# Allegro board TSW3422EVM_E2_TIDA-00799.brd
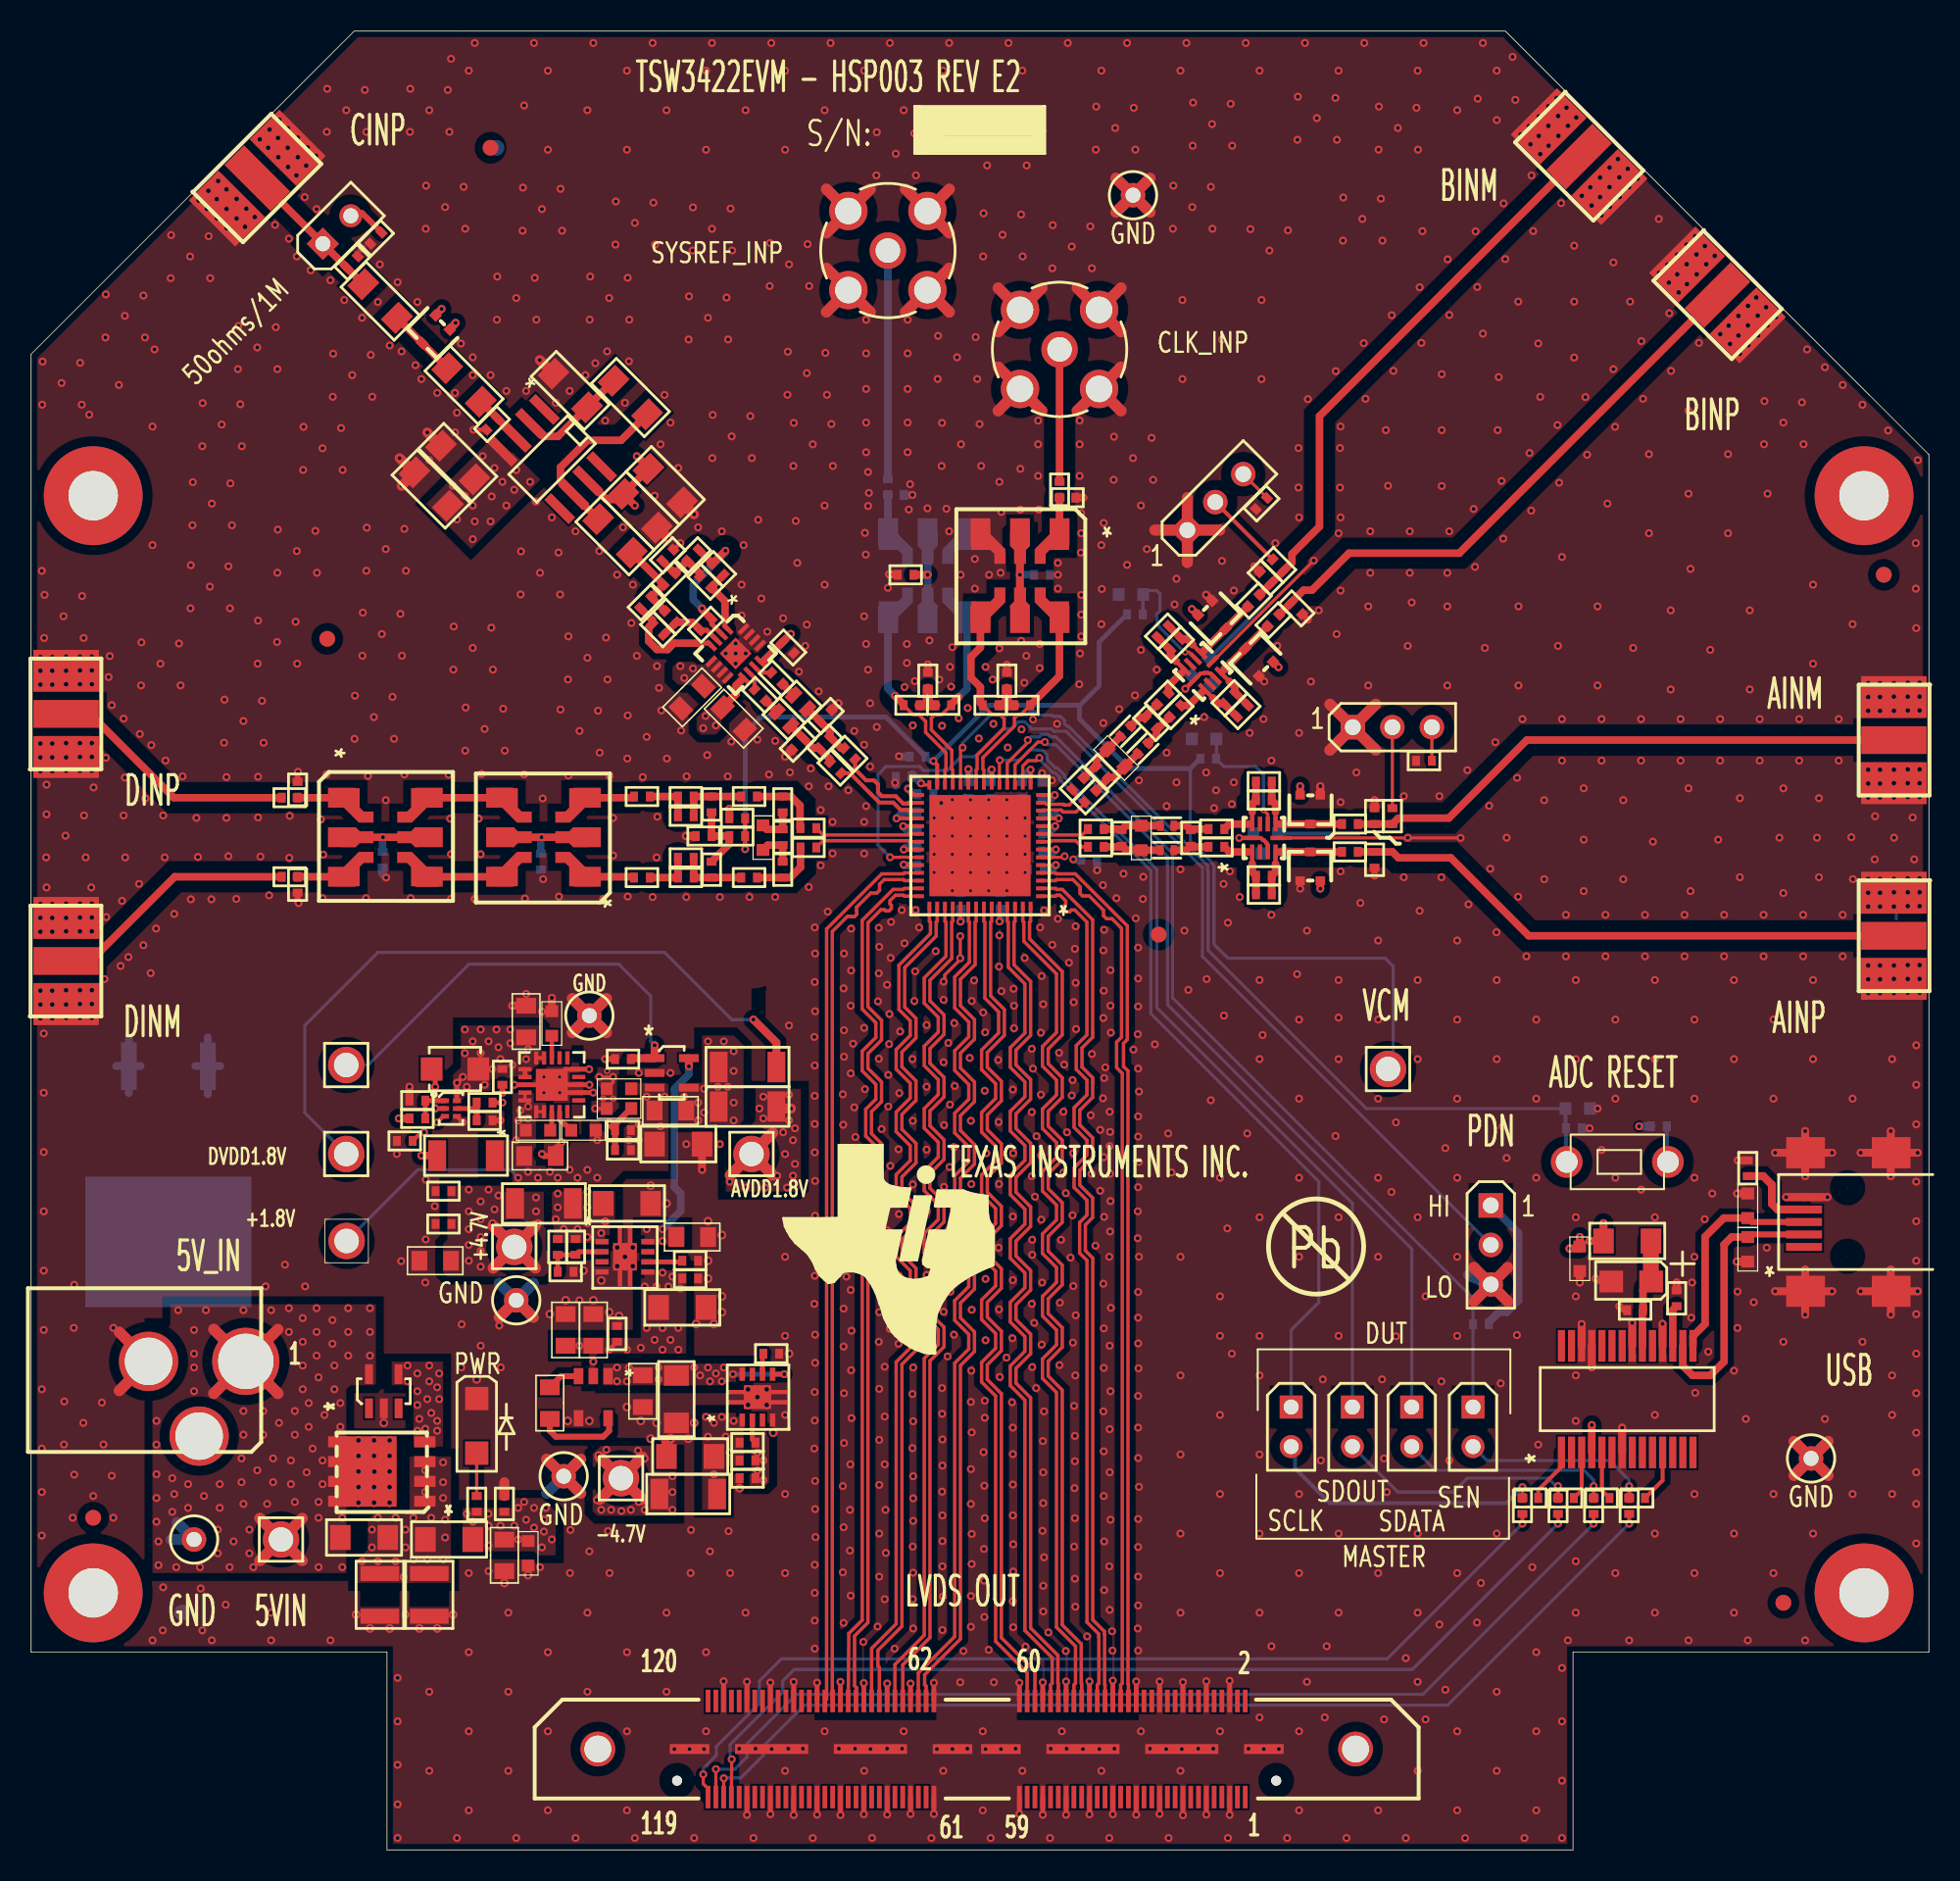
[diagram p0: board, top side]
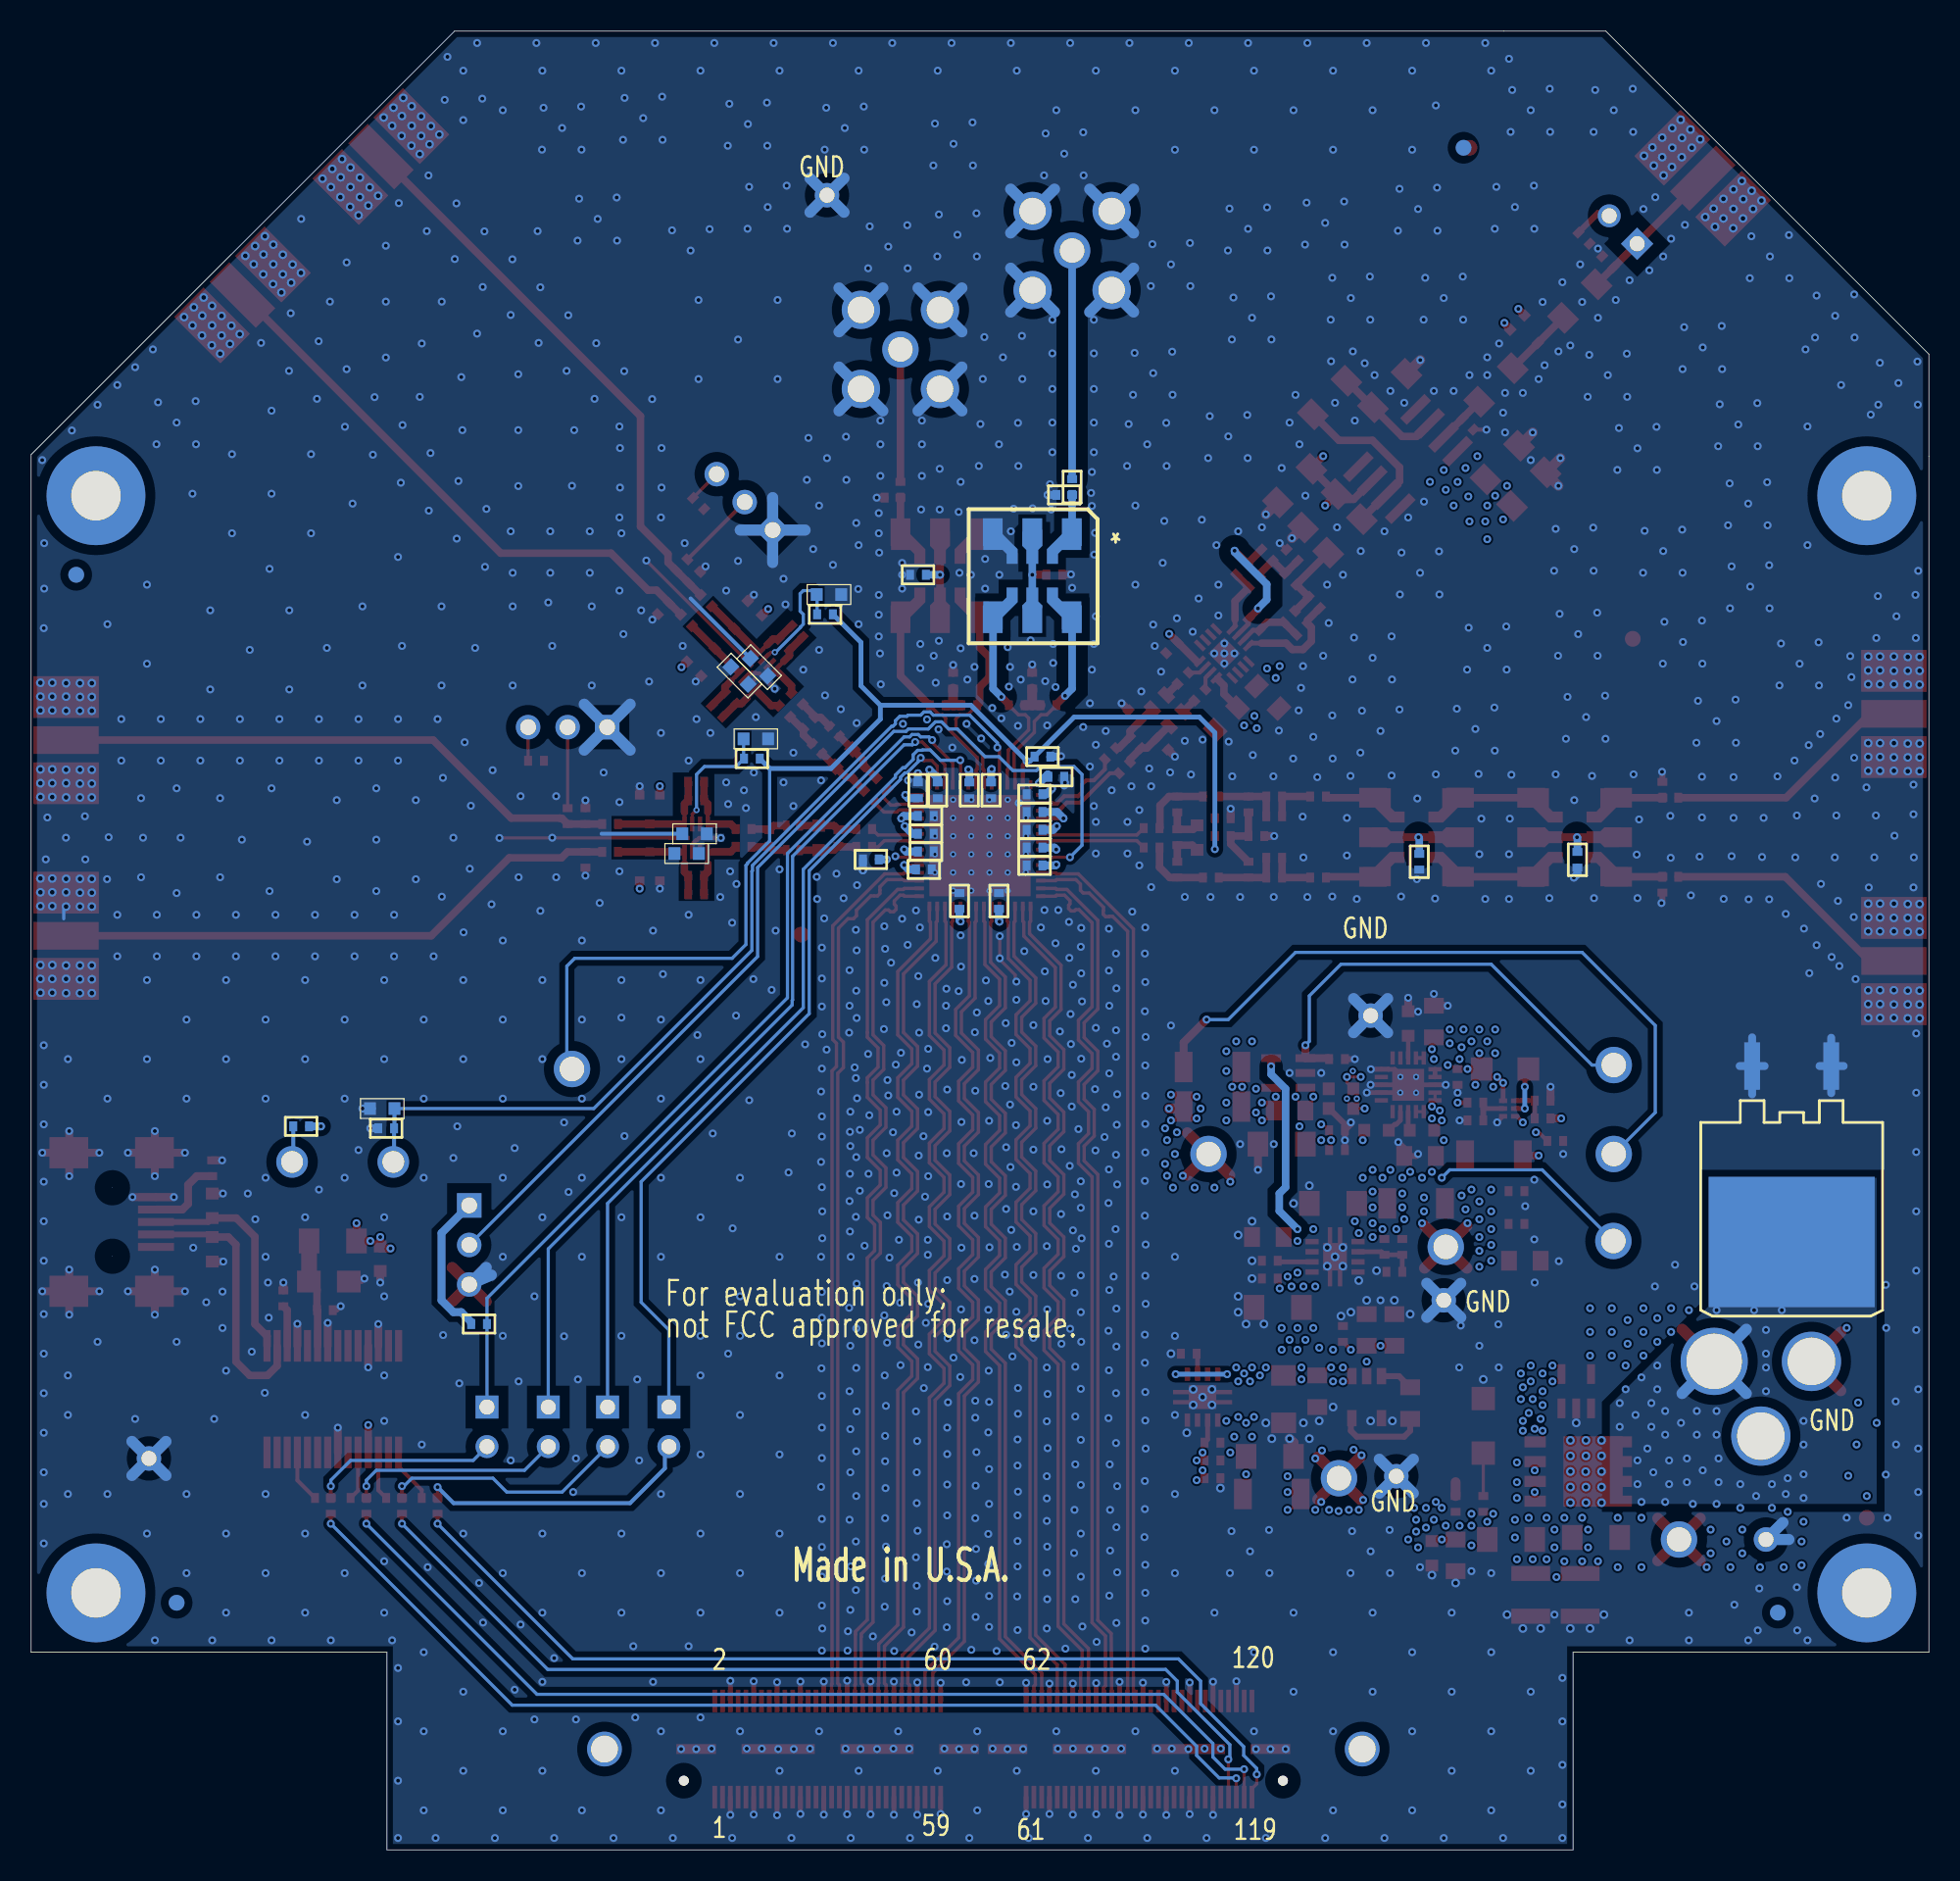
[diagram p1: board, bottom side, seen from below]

Outline 121.92 x 116.84 mm; copper layers: TOP, LYR2_GND, LYR3_PWR, LYR4_PWR, LYR5_GND, BOTTOM. Coordinates in mm from the lower left corner of the outline.
Outline path: 0,96.09 0,12.7 22.86,12.7 22.86,0 99.06,0 99.06,12.7 121.92,12.7 121.92,89.64 94.72,116.84 20.75,116.84 0,96.09

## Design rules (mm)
net group AIN: nets AINM AINP
net group BIN: nets BINM BINP
net group CIN: nets CINM CINP
net group CLKIN: nets CLKINM CLKINP
net group DA0: nets DA0M DA0P
net group DA1: nets DA1M DA1P
net group DB0: nets DB0M DB0P
net group DB1: nets DB1M DB1P
net group DC0: nets DC0M DC0P
net group DC1: nets DC1M DC1P
net group DCLK: nets DCLKM DCLKP
net group DD0: nets DD0M DD0P
net group DD1: nets DD1M DD1P
net group DIN: nets DINM DINP
net group FCLK: nets FCLKM FCLKP
net group SYSREF: nets SYSREFM SYSREFP

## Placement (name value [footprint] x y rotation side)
C1  .1uF  [0402]  39.24 62.46 0 top
C2  11pF  [0402]  48.28 65.05 90 top
C3  .1uF  [0402]  43.2 65.13 0 top
C4  .1uF  [0402]  45.36 66.27 0 top
C5  .1uF  [0402]  22.58 63.61 90 bottom
C6  .1uF  [0402]  32.74 63.48 90 bottom
C7  .1uF  [0402]  39.24 67.67 0 top
C8  5.6pF  [0402]  40.28 78.41 135 top
C9  16pF  [0402]  40.99 81.65 45 top
C10  5.6pF  [0402]  44.14 82.28 315 top
C11  5pF  [0402]  29.61 91.6 225 top
C12  82pF  [0402]  50.96 71.14 45 top
C13  5.6pF  [0402]  43.36 78.71 45 top
C14  .1uF  [1206]  27.41 89.13 135 top
C15  6.8uF  [1206]  25.7 87.42 135 top
C16  .1uF  [1206]  39.13 86.03 315 top
C17  6.8uF  [1206]  40.74 87.65 315 top
C18  .1uF  [0402]  48.64 77.24 315 top
C19  10uF  [0805]  42.47 74.04 225 top
C20  56pF  [0402]  71.95 72.39 315 top
C21  180pF  [0603]  69.7 70.15 315 top
C22  .01uF  [0603]  70.66 80.65 180 bottom
C23  10uF  [0805]  31.8 53.21 90 top
C24  0.01uF  [0603]  32.56 46.23 0 top
C25  56pF  [0402]  74.5 65.01 270 top
C26  180pF  [0603]  71.32 65.01 270 top
C27  .01uF  [0603]  75.36 71.37 180 bottom
C28  22uF  [0805]  32.69 44.58 0 top
C29  0.01uF  [0603]  33.45 53.09 90 top
C30  .1uF  [0402]  57.45 65.53 0 bottom
C31  .1uF  [0402]  57.45 66.67 0 bottom
C32  .1uF  [0402]  57.45 67.82 0 bottom
C33  .1uF  [0402]  56.06 68.94 180 bottom
C34  .1uF  [0402]  60.25 68.07 270 bottom
C35  .1uF  [0402]  61.65 68.07 270 bottom
C36  .1uF  [0402]  63.68 68.07 270 bottom
C37  .1uF  [0402]  67.97 63.63 0 bottom
C38  .1uF  [0402]  64.44 64.14 180 bottom
C39  .1uF  [0402]  57.45 64.39 0 bottom
C40  .1uF  [0402]  64.44 66.42 180 bottom
C41  .1uF  [0402]  64.44 65.28 180 bottom
C42  .1uF  [0402]  64.95 68.07 90 bottom
C43  .22uF  [0402]  64.57 62.99 180 bottom
C44  .22uF  [0402]  62.28 60.96 90 bottom
C45  .22uF  [0402]  59.74 60.96 90 bottom
C46  .22uF  [0402]  57.45 63.25 0 bottom
C47  .01uF  [0603]  99.36 47.62 0 bottom
C48  .1uF  [0402]  56.95 70.23 180 bottom
C49  .1uF  [0402]  66.07 87.38 90 top
C50  .1uF  [0402]  62.69 75.11 90 top
C51  .1uF  [0805]  25.96 37.85 180 top
C52  .1uF  [0402]  64.94 81.92 0 bottom
C53  .1uF  [0402]  55.04 87.55 90 bottom
C54  .1uF  [0402]  57.61 75.11 90 top
C55  .1uF  [0402]  26.49 42.32 180 top
C56  0  [0402]  56.18 81.92 180 top
C57  .01uF  [0603]  99.49 37.97 270 top
C58  .1uF  [0402]  103.05 34.67 180 top
C59  4.7uF  [TANT_A]  102.79 36.51 180 top
C60  47pF  [0603]  110.29 41.38 90 top
C61  47pF  [0603]  110.29 38.58 270 top
C62  .1uF  [0402]  105.71 35.43 90 top
C63  47uF  [1210]  25.58 16.38 270 top
C64  22uF  [1210]  22.4 16.38 90 top
C65  10uF  [0805]  30.4 18.92 270 top
C66  1.0uF  [0603]  31.93 19.05 270 top
C67  .1uF  [0402]  30.4 22.23 270 top
C68  2.2uF  [0402]  24 45.54 180 top
C69  .1uF  [0402]  38.02 46.23 0 top
C70  4.7uF  [0402]  30.28 49.66 270 top
C71  .1uF  [0402]  26.49 40.21 180 top
C72  10uF  [1206]  41.58 45.34 0 top
C75  10uF  [0805]  42.47 39.37 0 top
C76  .1uF  [0402]  42.34 36.7 180 top
C77  10uF  [1206]  41.83 34.85 0 top
C78  10uF  [1206]  38.28 41.53 0 top
C79  .01uF  [0402]  34.98 38.73 270 top
C80  .01uF  [0402]  42.34 37.85 0 top
C81  .01uF  [0402]  38.02 44.96 180 top
C82  10uF  [0805]  36.12 33.4 90 top
C83  .1uF  [0402]  37.64 33.15 270 top
C84  1uF  [0805]  34.34 33.4 90 top
C86  10uF  [1206]  41.45 28.96 270 top
C87  10uF  [1206]  42.34 25.27 180 top
C88  .01uF  [0402]  46.02 26.16 0 top
C89  1uF  [0402]  47.55 31.88 0 top
C90  1uF  [0805]  39.29 29.46 270 top
C91  1uF  [0805]  33.32 28.7 90 top
C94  .1uF  [0603]  75.15 75.98 45 bottom
C95  .1uF  [0603]  76.41 75.44 45 bottom
C96  .1uF  [0603]  79.81 64.01 0 bottom
C97  .1uF  [0603]  79.3 65.28 0 bottom
C98  .1uF  [0805]  45.14 72.67 315 top
C99  .1uF  [0402]  79.2 68.63 0 top
C100  .1uF  [0402]  72.71 78.27 45 top
C101  .1uF  [0402]  77.83 73.15 45 top
C102  .1uF  [0402]  79.2 61.39 0 top
C103  1uF  [0402]  79.04 86.49 225 top
C104  1uF  [0402]  89.48 69.97 180 top
D1  BAV99W  [SOT_323]  25.78 97.46 135 top
D2  BAV99W  [SOT_323]  78.67 76.53 45 top
D3  BAV99W  [SOT_323]  82.18 63.19 0 top
D4  LED GREEN  [LED_1206]  28.63 27.24 90 top
D5  MBRB2515L  [DIODE_MBRB2515L]  8.81 44.7 90 bottom
D6  BAV99W  [SOT_323]  76.09 79.11 225 top
D7  BAV99W  [SOT_323]  82.18 66.83 180 top
F1  FUSE 2.0A 63V FAST  [1206]  21.39 20.07 0 top
FB1  60 OHM @ 100MHz  [1206]  102.54 39.12 180 top
FB2  60 OHM @ 100MHz  [1206]  26.85 19.94 180 top
FB3  1K @ 100MHz  [1806]  46.02 50.29 180 top
FB4  1K @ 100MHz  [1806]  32.94 41.53 0 top
FB5  1K @ 100MHz  [1806]  42.21 22.86 0 top
FB6  1K @ 100MHz  [1806]  27.94 44.6 0 top
FB7  1K @ 100MHz  [1806]  46.02 47.75 180 top
J1  SMA_END_RND  [SMA_RECP_250X250]  2.25 57.1 0 top
J2  SMA_END_RND  [SMA_RECP_250X250]  2.25 72.98 0 top
J3  SMA_END_RND  [SMA_RECP_250X250]  14.53 107.39 315 top
J4  SMA_END_RND  [SMA_RECP_250X250]  108.34 99.89 225 top
J5  SMA_END_RND  [SMA_RECP_250X250]  99.45 108.78 225 top
J6  SMA_END_RND  [SMA_RECP_250X250]  119.67 58.72 180 top
J7  SMA_END_RND  [SMA_RECP_250X250]  119.67 71.29 180 top
J8  SMB_THVT_REC  [SMA_THVT_312X312]  66.07 96.39 270 top
J10  SMB_THVT_REC  [SMA_THVT_312X312]  55.04 102.74 0 top
J12  QTH-060-01-F-D-A-RT1  [CON_SMVT_120POS_QTH_SAMTEC_RT1]  79.96 4.45 180 top
J13  CONN, USB MINI AB, SMT  [CON_SMRT_USBMNE20_F]  117.35 40.34 180 top
J14  CONN JACK PWR  [CON_RAPC722_JACK_THVT_3]  10.67 31.38 270 top
JP1  HEADER, 2POS, .100  [HDR_THVT_1X2_100_M]  18.74 103.18 135 top
JP2  HEADER, 3POS, .100  [HDR_THVT_1X3_100_M]  93.78 41.4 0 top
JP3  HEADER, 2POS, .100  [HDR_THVT_1X2_100_M]  80.95 28.45 0 top
JP4  HEADER, 2POS, .100  [HDR_THVT_1X2_100_M]  88.7 28.45 0 top
JP5  HEADER, 2POS, .100  [HDR_THVT_1X2_100_M]  92.63 28.45 0 top
JP6  HEADER, 2POS, .100  [HDR_THVT_1X2_100_M]  84.89 28.45 0 top
JP7  HEADER, 3POS, .100  [HDR_THVT_1X3_100_M]  74.28 84.79 135 top
JP8  HEADER, 3POS, .100  [HDR_THVT_1X3_100_M]  84.91 72.13 90 top
L1  39nH  [0402]  42.06 63.73 180 top
L2  11pF  [0603]  47.01 65.03 270 top
L3  39nH  [0402]  42.06 66.4 180 top
L4  240nH  [IND_0603]  48.36 72.67 315 top
L5  240nH  [IND_0603]  49.44 73.74 315 top
L6  390nH  [IND_0402]  70.32 71.87 225 top
L7  390nH  [IND_0402]  71.43 70.76 225 top
L8  390nH  [IND_0402]  72.97 65.8 180 top
L9  390nH  [IND_0402]  72.97 64.22 180 top
L10  2.2uH  [1008]  27.23 50.17 180 top
NOREF  -  [unnamed]  19.02 77.8 0 top
NOREF#2  -  [#2]  80.52 37.49 0 top
NOREF#3  -  [#2]  0 12.7 0 top
NOREF#4  -  [unnamed#3]  3.99 87 0 top
NOREF#5  -  [unnamed]  119.02 81.92 0 top
NOREF#6  -  [unnamed]  29.51 109.35 0 top
NOREF#7  -  [#2]  -294.27 -158.75 0 top
NOREF#8  -  [unnamed]  3.99 21.34 0 top
NOREF#9  -  [unnamed#3]  117.75 87 0 top
NOREF#10  -  [#2]  3.99 16.51 90 top
NOREF#11  -  [#2]  22.86 0 0 top
NOREF#12  -  [#2]  -286.46 355.6 0 top
NOREF#13  -  [#2]  3.99 16.51 0 top
NOREF#14  -  [#2]  18.17 -22.55 0 top
NOREF#15  -  [#2]  -14.76 124.49 0 top
NOREF#16  -  [unnamed#3]  117.75 16.51 0 top
NOREF#17  -  [#2]  49.7 109.54 0 top
NOREF#18  -  [#2]  -276.43 355.97 0 top
NOREF#19  -  [#2]  0 12.7 0 top
NOREF#20  -  [#2]  22.86 0 90 top
NOREF#21  -  [#2]  0 12.7 0 top
NOREF#22  -  [#2]  20.75 116.84 0 top
NOREF#23  -  [#2]  141.38 123.77 0 top
NOREF#24  -  [#2]  141.38 -14.66 0 top
NOREF#25  -  [#2]  -294.13 -159.02 0 top
NOREF#26  -  [#2]  0 12.7 90 top
NOREF#27  -  [unnamed]  112.57 15.88 0 top
NOREF#28  -  [unnamed]  72.44 58.8 0 top
NOREF#29  -  [unnamed#3]  3.99 16.51 0 top
NOREF#30  -  [#2]  3.99 16.51 90 top
NOREF#31  -  [#2]  562.28 -119.51 0 top
NOREF#32  -  [#2]  94.72 116.84 0 top
NOREF#33  -  [#2]  3.99 87 0 top
NOREF#34  -  [#2]  134.64 34.35 0 top
NOREF#35  -  [#2]  99.06 0 90 top
NOREF#36  -  [#2]  81.31 35.03 180 bottom
NOREF#37  -  [unnamed]  9.7 15.24 180 bottom
NOREF#38  -  [unnamed]  29.9 109.35 180 bottom
NOREF#39  -  [unnamed]  112.57 15.88 180 bottom
NOREF#40  -  [unnamed]  119.02 81.92 180 bottom
NOREF#41  -  [#2]  111.61 14.66 180 bottom
Q1  CSD18532Q5  [SON_Q5B_8]  22.53 24.31 180 top
R1  49.9  [0402]  42.06 62.46 0 top
R2  0  [0402]  46.13 62.46 0 top
R3  0  [0402]  49.94 64.39 0 top
R4  0  [0402]  16.61 62.51 0 top
R5  49.9  [0402]  48.28 62.97 90 top
R6  24.9  [0402]  43.71 62.97 90 top
R7  0  [0402]  17.12 62.01 270 top
R8  0  [0402]  45.36 65.13 0 top
R9  0  [0402]  16.61 67.59 0 top
R10  24.9  [0402]  43.71 67.16 90 top
R11  49.9  [0402]  48.28 67.16 90 top
R12  0  [0402]  17.12 68.1 90 top
R13  49.9  [0402]  42.06 67.67 0 top
R14  0  [0402]  46.13 67.67 0 top
R15  0  [0402]  49.94 65.64 0 top
R16  200  [1206]  38.5 93.3 315 top
R17  249  [0402]  39.49 80.14 225 top
R18  442  [1206]  37.51 84.41 315 top
R19  542  [0402]  41.08 79.22 315 top
R20  80.6  [0402]  46.83 74.19 315 top
R21  5.1  [0402]  51.68 69.52 315 top
R22  150  [1206]  22.42 99.5 315 top
R23  5.1  [0402]  67.24 68.49 225 top
R24  422  [0402]  68.81 69.25 135 top
R25  316  [0402]  49.26 71.05 45 top
R26  5.1  [0402]  68.04 67.68 225 top
R27  542  [0402]  42.52 83.17 45 top
R28  200  [1206]  34.64 93.75 135 top
R29  249  [0402]  43.33 81.47 315 top
R30  442  [0402]  40.9 83.17 225 top
R31  49.9  [0402]  22.15 103.54 225 top
R32  1M  [0402]  20.63 102.01 225 top
R33  80.6  [0402]  47.91 75.27 315 top
R34  5.1  [0402]  52.58 70.42 315 top
R35  316  [0402]  51.05 72.85 225 top
R36  402  [0402]  76.99 74 225 top
R37  402  [0402]  73.55 77.43 225 top
R38  61.9  [0402]  81.29 79.75 315 top
R39  34.8  [0402]  72.71 73.96 225 top
R40  162  [0402]  79.81 78.99 225 top
R41  49.9  [0402]  80.12 82.54 135 top
R42  162  [0402]  78.55 80.25 225 top
R43  34.8  [0402]  73.52 73.15 225 top
R44  61.9  [0402]  79.31 81.73 135 top
R45  100  [0402]  70.92 79.38 0 bottom
R46  402  [0402]  79.2 62.58 180 top
R47  402  [0402]  79.2 67.44 180 top
R48  61.9  [0402]  86.31 63.61 270 top
R49  34.8  [0402]  76.15 65.58 180 top
R50  5.1  [0402]  68.4 65.58 180 top
R51  162  [0402]  84.72 64.11 180 top
R52  162  [0402]  84.72 65.9 180 top
R53  34.8  [0402]  76.15 64.44 180 top
R54  61.9  [0402]  86.31 66.41 90 top
R55  100  [0402]  75.62 70.1 0 bottom
R56  1k  [0402]  93.14 33.78 180 bottom
R57  1k  [0402]  104.57 46.48 0 bottom
R58  10k  [0402]  99.11 46.36 0 bottom
R59  49.9  [0402]  66.58 86.87 0 top
R60  100  [0402]  63.68 73.53 0 top
R61  100  [0402]  61.65 73.53 0 top
R62  422  [0402]  70.05 65.01 90 top
R63  49.9  [0402]  55.55 87.05 0 bottom
R64  100  [0402]  58.6 73.53 0 top
R65  100  [0402]  56.57 73.53 0 top
R67  0  [0402]  95.81 22.1 90 top
R68  0  [0402]  100.38 22.1 90 top
R69  0  [0402]  98.09 22.1 90 top
R70  0  [0402]  102.67 22.1 90 top
R71  22  [0402]  96.32 22.61 0 top
R72  22  [0402]  100.89 22.61 0 top
R73  22  [0402]  98.6 22.61 0 top
R74  0  [0402]  110.29 43.79 90 top
R75  22  [0402]  103.17 22.61 0 top
R76  1k  [0402]  28.63 22.23 90 top
R77  0  [0402]  29.13 48.01 180 top
R78  0  [0402]  24.82 46.99 0 top
R79  0  [0402]  29.13 46.86 0 top
R80  0  [0402]  24.82 48.13 180 top
R81  10k  [0603]  35.48 46.23 180 top
R82  25.5K  [0402]  38.02 50.8 180 top
R83  34.8k  [0402]  33.83 38.73 270 top
R84  12k  [0402]  34.34 37.13 0 top
R85  649k  [0402]  46.02 25.02 0 top
R86  215k  [0402]  46.02 23.88 180 top
R87  5.1k  [0603]  37.77 48.89 0 top
R88  0.2  [0805]  41.07 47.5 180 top
R89  49.9  [1206]  27.81 94.11 315 top
R90  10k  [0603]  37.77 47.62 0 top
R91  5.1  [0402]  68.4 64.44 180 top
R92  49.9  [0402]  87.45 66.41 90 top
SW1  SW, PUSHBUTTON  [SW_RESET_PTS635]  101.9 44.2 0 top
T1  ADT1-1WT+  [TFMR_6_RF_DUAL_FOOTPRINT]  22.76 65.05 270 top
T2  ADT1-1WT+  [TFMR_6_RF_DUAL_FOOTPRINT]  32.92 65.05 90 top
T3  ADT4-6WT+  [TFMR_6_RF_DUAL_FOOTPRINT]  63.53 81.86 180 top
T4  ADT4-6WT+  [TFMR_6_RF_DUAL_FOOTPRINT]  57.6 81.86 0 bottom
TP1  RED  [TESTPOINT_62DRILL_THM]  87.17 50.17 0 top
TP2  RED  [TESTPOINT_62DRILL_THM]  16.05 19.94 0 top
TP3  BLK  [TP_THVT_060_RND_GND]  10.46 19.94 0 top
TP4  RED  [TESTPOINT_62DRILL_THM]  20.24 50.42 0 top
TP5  RED  [TESTPOINT_62DRILL_THM]  31.04 38.73 0 top
TP6  BLK  [TP_THVT_060_RND_GND]  35.86 53.59 0 top
TP7  RED  [TESTPOINT_62DRILL_THM]  37.9 23.88 0 top
TP8  BLK  [TP_THVT_060_RND_GND]  31.17 35.31 0 top
TP9  BLK  [TP_THVT_060_RND_GND]  34.21 24 0 top
TP10  BLK  [TP_THVT_060_RND_GND]  70.79 106.3 0 top
TP11  RED  [TESTPOINT_62DRILL_THM]  46.28 44.7 0 top
TP12  RED  [TESTPOINT_62DRILL_THM]  20.24 44.7 0 top
TP13  RED  [TESTPOINT_62DRILL_THM]  20.27 39.12 0 top
TP14  BLK  [TP_THVT_060_RND_GND]  114.35 25.15 0 top
U1  OPA656UB  [SO_8_197X157_50]  33.47 89.35 315 top
U2  THS4541  [VQFN_16_124X124_PWRPAD]  45.26 76.86 315 top
U3  THS4541  [QFN_10_83X83_RUN]  75.27 75.71 135 top
U4  THS4541  [QFN_10_83X83_RUN]  79.2 65.01 90 top
U5  ADC3422  [QFN_56_319X319_0P5MM]  60.96 64.52 180 top
U6  FT245RL  [SSOP_28_413X221_26]  102.54 28.96 90 top
U7  TPS2400  [DBV5]  22.66 29.46 90 top
U8  TPS6223X  [SON_6_DRY_1P5MMX1P0MM]  26.97 47.62 0 top
U9  TPS7A8300  [VQFN_20_138X138_0P50_RGR]  33.45 49.15 90 top
U10  TPS7A4901  [SON_8_3MMX3MM_0P65MM]  38.15 38.1 0 top
U11  TPS60403  [SOT-23_5_63X114_DBV]  36.12 29.08 270 top
U12  TPS7A3001  [SON_8_3MMX3MM_0P65MM]  46.66 29.08 90 top
U13  INA138  [DBV5]  41.16 49.91 0 top

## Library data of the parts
C1 C7 = CAP_0402_0.1uF: tolerance: 10%
C2 = CAP0603: tolerance: 1%
C3 C4 = CAP_0402_0.1uF_H: tolerance: 10%
C5 C6 C50 C52 C54 C99-C102 = CAP0603: tolerance: 10%
C8 C10 C13 = CAP_0402_5.6pF
C9 = CAP_0402_16pF
C11 = CAP_0402_5pF
C12 = CAP_0402_82pF
C14 C16 = CAP_1206_.1uF
C15 C17 = CAP_1206_6.8uF
C18 C55 C71 = CAP_0402_0.1uF
C19 = CAP_0805_10uF_16V: tolerance: 10%, 10V, X7R
C20 C25 = CAP_0402_56pF
C21 C26 = CAP_0603_180pF_.1%
C22 C24 C27 C29 = CAP_0603_0.01uF
C23 = CAP_0805_10uF_16V: tolerance: 10%, 16V, X5R
C28 = CAP_0805_22uF
C30-C42 C48 C49 C53 = CAP0402_0: tolerance: 10%
C43-C46 = CAP0402_0: tolerance: +/-10%
C47 = CAP NP_0: tolerance: 5%
C51 = CAP_0805_.1uF_16V: tolerance: 10%, 50V, X7R
C56 C57 C60 C61 = CAP0603
C58 C62 C63 C66 = CAP NP_0: tolerance: 10%
C59 = CAP POL-B_10uF_10V: tolerance: 10%
C64 = CAP_1210_22uF
C65 = CAP NP_1: tolerance: 10%
C67 C69 C76 C81 C83 = CAPACITOR_NP_1: tolerance: 10%
C68 = CAP_0402_2.2uF
C70 = CAP_0402_4.7uF
C72 C77 C78 C86 C87 = CAP_1206_10uF
C75 C82 = CAP_1206_2.2uF: tolerance: 10%
C79 C80 C88 = CAP_0402_0.01uF
C84 C90 C91 = CAP_0805_1uF_16V: tolerance: 10%, 25V, X5R
C89 C103 C104 = CAP_0402_1uF
C94-C97 = CAP_0805_0.1uF_HF_10V: tolerance: 20%
C98 = CAP_0805_0.1uF_HF_10V: tolerance: 5%
D1-D3 D6 D7 = DIODE_DUAL_BAV99W
D4 = LED_GREEN_0
D5 = MBRB2515L_5
F1 = FUSE_0
FB1-FB7 = FERRITE_BEAD
J1-J7 = SMA-END_PLUG_ROUND_0
J8 J10 = SMA-THVT_142-0701-201_REC
J12 = CON_SMVT_120POS_QTH_SAMTEC
J13 = USB_MINI_AB_MNE20-5G5P10
J14 = CONN JACK PWR
JP1 JP3-JP6 = JUMPER_1X2_100
JP2 JP7 JP8 = Jumper_1x3_smt
L1 L3 = IND_1
L2 = IND0603: tolerance: 1%
L4 L5 = IND_0603_H_0
L6-L9 = IND_0402_250nH_H
L10 = IND_SM_1008_2.2uH
Q1 = CSD18532Q5B
R1 R5 R11 R13 = Res_0402_49.9: tolerance: 1%
R2 R14 = Res_0402_Zero
R3 R15 = Res_0402_4.99
R4 R8 R12 R74 = R: tolerance: 5%
R6 R10 = Res_0402_24.9
R7 R9 = RES0603: tolerance: 5%
R16 R28 = Res_1206_200_.1%: tolerance: .1%
R17 R29 = Res_0402_249
R18 = Res_1206_442: tolerance: 1%
R19 R27 = Res_0402_542_H
R20 R33 = Res_0402_80.6_H
R21 R23 R26 R34 R50 R91 = Res_0402_5.1_H
R22 = Res_1206_150: tolerance: 1%
R24 R30 R62 = Res_0402_442_H
R25 R35 = Res_0402_316_H
R31 R41 R92 = Res_0402_49.9
R32 = Res_0402_1M_H
R36 R37 R46 R47 = Res_0402_402_H
R38 R44 R48 R54 = Res_0402_61.9
R39 R43 R49 R53 = Res_0402_34.8_H
R40 R42 R51 R52 = Res_0402_162_H
R45 R55 = Res_0402_100_H
R56 R57 R60 R61 R64 R65 = RES0603: tolerance: 1%
R58 = R_4: tolerance: 1%
R59 R63 = RES0603
R67-R70 = R
R71-R73 R75 R88 = R: tolerance: 1%
R76-R80 = Res_0402_1k
R81 = Res_0603_10k
R82 = R_1: tolerance: 1%
R83 = Res_0402_34.8k: tolerance: .1%
R84 = Res_0402_12k: tolerance: .1%
R85 = Res_0402_649k
R86 = Res_0402_215k
R87 = Res_0603_5.1K: tolerance: .1%
R89 = Res_1206_49.9_.1%: tolerance: .1%
R90 = Res_0603_10k: tolerance: .1%
SW1 = SW PUSHBUTTON_1
T1 T2 = TFMR_6_WBC1-1TLB
T3 T4 = XFMR_6_JTX-4-10T
TP1 = TP_THVT_060_RND-RED
TP2 TP3 TP6 TP8-TP10 TP14 = TESTLOOP_BLACK
TP4 = TESTPOINT_BLUE
TP5 TP7 TP11-TP13 = TESTPOINT_RED
U1 = OPA656UB
U2 = THS4541_VQFN
U3 U4 = THS4541
U5 = ADC34XX_QFN56
U6 = FT245RL_0
U7 = TPS2400
U8 = TPS6223X
U9 = TPS7A8300
U10 = TPS7A49
U11 = TPS6040x
U12 = TPS7A30
U13 = INA138

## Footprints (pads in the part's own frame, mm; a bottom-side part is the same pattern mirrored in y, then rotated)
0402
  rect 0.508x0.635 smd: 1(-0.508,0) 2(0.508,0)
0603
  rect 0.762x0.813 smd: 1(-0.787,0) 2(0.787,0)
0805
  rect 1.016x1.27 smd: 1(-1.016,0) 2(1.016,0)
1008
  rect 1.397x1.499 smd: 1(-1.499,0) 2(1.499,0)
1206
  rect 1.321x1.6 smd: 1(-1.524,0) 2(1.524,0)
1210
  rect 0.965x2.489 smd: 1(-1.372,0) 2(1.372,0)
1806
  rect 1.143x1.956 smd: 1(-1.854,0) 2(1.854,0)
CON_RAPC722_JACK_THVT_3
  round 4.318 hole 3.556: 1(0,3.124)
  round 3.81 hole 3.048: 2(0,-3.124) 3(4.801,0.127)
CON_SMRT_USBMNE20_F
  round 0.025 hole 0.991 unplated: (0.65,2.2) (0.65,-2.2)
  rect 2.311x0.508 smd: 1(3.45,1.6) 2(3.45,0.8) 3(3.45,0) 4(3.45,-0.8) 5(3.45,-1.6)
  rect 2.489x2.007 smd: 6(-2.15,-4.45) 7(3.35,-4.45) 8(3.35,4.45) 9(-2.15,4.45)
CON_SMVT_120POS_QTH_SAMTEC_RT1
  round 2.235 hole 1.727: (-5.127,-2.032) (43.552,-2.032)
  round 0.635 hole 1.016 unplated: (-0.03,0) (38.461,0)
  rect 0.305x1.448 smd: 1(1.958,1.054) 2(1.958,-5.118) 3(2.459,1.054) 4(2.459,-5.118) 5(2.959,1.054) 6(2.959,-5.118) 7(3.459,1.054) 8(3.459,-5.118) 9(3.96,1.054) 10(3.96,-5.118) 11(4.46,1.054) 12(4.46,-5.118) 13(4.961,1.054) 14(4.961,-5.118) 15(5.461,1.054) 16(5.461,-5.118) 17(5.961,1.054) 18(5.961,-5.118) 19(6.462,1.054) 20(6.462,-5.118) 21(6.962,1.054) 22(6.962,-5.118) 23(7.463,1.054) 24(7.463,-5.118) 25(7.963,1.054) 26(7.963,-5.118) 27(8.463,1.054) 28(8.463,-5.118) 29(8.964,1.054) 30(8.964,-5.118) 31(9.464,1.054) 32(9.464,-5.118) 33(9.964,1.054) 34(9.964,-5.118) 35(10.465,1.054) 36(10.465,-5.118) 37(10.965,1.054) 38(10.965,-5.118) 39(11.466,1.054) 40(11.466,-5.118) 41(11.966,1.054) 42(11.966,-5.118) 43(12.466,1.054) 44(12.466,-5.118) 45(12.967,1.054) 46(12.967,-5.118) 47(13.467,1.054) 48(13.467,-5.118) 49(13.967,1.054) 50(13.967,-5.118) 51(14.468,1.054) 52(14.468,-5.118) 53(14.968,1.054) 54(14.968,-5.118) 55(15.469,1.054) 56(15.469,-5.118) 57(15.969,1.054) 58(15.969,-5.118) 59(16.469,1.054) 60(16.469,-5.118) 61(21.961,1.054) 62(21.961,-5.118) 63(22.461,1.054) 64(22.461,-5.118) 65(22.962,1.054) 66(22.962,-5.118) 67(23.462,1.054) 68(23.462,-5.118) 69(23.962,1.054) 70(23.962,-5.118) 71(24.463,1.054) 72(24.463,-5.118) 73(24.963,1.054) 74(24.963,-5.118) 75(25.463,1.054) 76(25.463,-5.118) 77(25.964,1.054) 78(25.964,-5.118) 79(26.464,1.054) 80(26.464,-5.118) 81(26.965,1.054) 82(26.965,-5.118) 83(27.465,1.054) 84(27.465,-5.118) 85(27.965,1.054) 86(27.965,-5.118) 87(28.466,1.054) 88(28.466,-5.118) 89(28.966,1.054) 90(28.966,-5.118) 91(29.467,1.054) 92(29.467,-5.118) 93(29.967,1.054) 94(29.967,-5.118) 95(30.467,1.054) 96(30.467,-5.118) 97(30.968,1.054) 98(30.968,-5.118) 99(31.468,1.054) 100(31.468,-5.118) 101(31.968,1.054) 102(31.968,-5.118) 103(32.469,1.054) 104(32.469,-5.118) 105(32.969,1.054) 106(32.969,-5.118) 107(33.47,1.054) 108(33.47,-5.118) 109(33.97,1.054) 110(33.97,-5.118) 111(34.47,1.054) 112(34.47,-5.118) 113(34.971,1.054) 114(34.971,-5.118) 115(35.471,1.054) 116(35.471,-5.118) 117(35.971,1.054) 118(35.971,-5.118) 119(36.472,1.054) 120(36.472,-5.118)
  rect 2.54x0.635 smd: 121(0.765,-2.032) 124(17.656,-2.032) 125(20.767,-2.032) 128(37.658,-2.032)
  rect 4.699x0.635 smd: 122(6.035,-2.032) 123(12.385,-2.032) 126(26.038,-2.032) 127(32.388,-2.032)
DBV5
  rect 1.27x0.508 smd: 1(-1.1,0.95) 2(-1.1,0) 3(-1.1,-0.95) 4(1.1,-0.95) 5(1.1,0.95)
DIODE_MBRB2515L
  rect 3.048x1.016 smd: 1(5.652,-2.54) 3(5.652,2.54)
  round 0.013 smd: 2(5.652,0)
  rect 8.382x10.668 smd: 4(-5.652,0)
HDR_THVT_1X2_100_M
  rect 1.473x1.473 hole 0.965: 1(0,0)
  round 1.473 hole 0.965: 2(0,-2.54)
HDR_THVT_1X3_100_M
  rect 1.575x1.575 hole 1.016: 1(0,0)
  round 1.575 hole 1.016: 2(0,-2.54) 3(0,-5.08)
IND_0402
  rect 0.406x0.66 smd: 1(-0.432,0) 2(0.432,0)
IND_0603
  rect 0.635x1.016 smd: 1(-0.635,0) 2(0.635,0)
LED_1206
  rect 1.499x1.499 smd: 1(-1.753,0) 2(1.753,0)
QFN_10_83X83_RUN
  rect 0.95x0.28 smd: 1(-0.895,0.75) 2(-0.895,0.25) 3(-0.895,-0.25) 4(-0.895,-0.75) 6(0.895,-0.75) 7(0.895,-0.25) 8(0.895,0.25) 9(0.895,0.75)
  rect 0.28x0.95 smd: 5(0,-0.895) 10(0,0.895)
QFN_56_319X319_0P5MM
  rect 0.6x0.25 smd: 1(-3.9,3.25) 2(-3.9,2.75) 3(-3.9,2.25) 4(-3.9,1.75) 5(-3.9,1.25) 6(-3.9,0.75) 7(-3.9,0.25) 8(-3.9,-0.25) 9(-3.9,-0.75) 10(-3.9,-1.25) 11(-3.9,-1.75) 12(-3.9,-2.25) 13(-3.9,-2.75) 14(-3.9,-3.25) 29(3.9,-3.25) 30(3.9,-2.75) 31(3.9,-2.25) 32(3.9,-1.75) 33(3.9,-1.25) 34(3.9,-0.75) 35(3.9,-0.25) 36(3.9,0.25) 37(3.9,0.75) 38(3.9,1.25) 39(3.9,1.75) 40(3.9,2.25) 41(3.9,2.75) 42(3.9,3.25)
  rect 0.25x0.6 smd: 15(-3.25,-3.9) 16(-2.75,-3.9) 17(-2.25,-3.9) 18(-1.75,-3.9) 19(-1.25,-3.9) 20(-0.75,-3.9) 21(-0.25,-3.9) 22(0.25,-3.9) 23(0.75,-3.9) 24(1.25,-3.9) 25(1.75,-3.9) 26(2.25,-3.9) 27(2.75,-3.9) 28(3.25,-3.9) 43(3.25,3.9) 44(2.75,3.9) 45(2.25,3.9) 46(1.75,3.9) 47(1.25,3.9) 48(0.75,3.9) 49(0.25,3.9) 50(-0.25,3.9) 51(-0.75,3.9) 52(-1.25,3.9) 53(-1.75,3.9) 54(-2.25,3.9) 55(-2.75,3.9) 56(-3.25,3.9)
  rect 6.502x6.502 smd: 57(0,0)
SMA_RECP_250X250
  rect 4.191x1.778 smd: 1(0,0)
  rect 4.191x2.667 smd: 2(0,2.769) 3(0,-2.769) 4(0,2.769) 5(0,-2.769)
SMA_THVT_312X312
  round 2.337 hole 1.575: 1(0,0)
  round 2.464 hole 1.702: 2(-2.54,2.54) 3(2.54,2.54) 4(2.54,-2.54) 5(-2.54,-2.54)
SO_8_197X157_50
  rect 2.21x0.61 smd: 1(-2.603,1.905) 2(-2.603,0.635) 3(-2.603,-0.635) 4(-2.603,-1.905) 5(2.603,-1.905) 6(2.603,-0.635) 7(2.603,0.635) 8(2.603,1.905)
SON_6_DRY_1P5MMX1P0MM
  rect 0.52x0.3 smd: 1(-0.385,0.5) 2(-0.385,0) 3(-0.385,-0.5) 4(0.385,-0.5) 5(0.385,0) 6(0.385,0.5)
SON_8_3MMX3MM_0P65MM
  rect 0.85x0.35 smd: 1(-1.475,0.975) 2(-1.475,0.325) 3(-1.475,-0.325) 4(-1.475,-0.975) 5(1.475,-0.975) 6(1.475,-0.325) 7(1.475,0.325) 8(1.475,0.975)
  rect 1.5x1.75 smd: 9(0,0)
SON_Q5B_8
  rect 1.372x0.711 smd: 1(-2.767,1.905) 2(-2.767,0.635) 3(-2.767,-0.635) 4(-2.767,-1.905) 5(2.767,-1.905) 6(2.767,-0.635) 7(2.767,0.635) 8(2.767,1.905)
SOT-23_5_63X114_DBV
  rect 1.041x0.61 smd: 1(-1.35,0.95) 2(-1.35,0) 3(-1.35,-0.95) 4(1.35,-0.95) 5(1.35,0.95)
SOT_323
  rect 0.61x0.559 smd: 1(-0.648,-0.927) 2(0.648,-0.927) 3(0,0.927)
SSOP_28_413X221_26
  rect 2.032x0.457 smd: 1(-3.425,4.225) 2(-3.425,3.575) 3(-3.425,2.925) 4(-3.425,2.275) 5(-3.425,1.625) 6(-3.425,0.975) 7(-3.425,0.325) 8(-3.425,-0.325) 9(-3.425,-0.975) 10(-3.425,-1.625) 11(-3.425,-2.275) 12(-3.425,-2.925) 13(-3.425,-3.575) 14(-3.425,-4.225) 15(3.425,-4.225) 16(3.425,-3.575) 17(3.425,-2.925) 18(3.425,-2.275) 19(3.425,-1.625) 20(3.425,-0.975) 21(3.425,-0.325) 22(3.425,0.325) 23(3.425,0.975) 24(3.425,1.625) 25(3.425,2.275) 26(3.425,2.925) 27(3.425,3.575) 28(3.425,4.225)
SW_RESET_PTS635
  round 2.032 hole 1.397: 1(-3.251,0) 2(3.251,0)
TANT_A
  rect 1.524x1.397 smd: 1(-1.283,0) 2(1.283,0)
TESTPOINT_62DRILL_THM
  round 2.337 hole 1.575: 1(0,0)
TFMR_6_RF_DUAL_FOOTPRINT
  rect 1.27x1.778 smd: 1(-2.54,-2.794) 2(0,-2.794) 3(2.54,-2.794) 4(2.54,2.794) 5(0,2.794) 6(-2.54,2.794)
TP_THVT_060_RND_GND
  round 1.575 hole 0.965: 1(0,0)
unnamed
  round 1.016 smd: 1(0,0)
unnamed#3
  round 6.35 hole 3.175: (0,0)
VQFN_16_124X124_PWRPAD
  rect 0.838x0.279 smd: 1(-1.473,0.749) 2(-1.473,0.249) 3(-1.473,-0.249) 4(-1.473,-0.749) 9(1.473,-0.749) 10(1.473,-0.249) 11(1.473,0.249) 12(1.473,0.749)
  rect 0.279x0.838 smd: 5(-0.749,-1.473) 6(-0.249,-1.473) 7(0.249,-1.473) 8(0.749,-1.473) 13(0.749,1.473) 14(0.249,1.473) 15(-0.249,1.473) 16(-0.749,1.473)
  rect 1.448x1.448 smd: 17(0,0)
VQFN_20_138X138_0P50_RGR
  rect 0.85x0.28 smd: 1(-1.725,1) 2(-1.725,0.5) 3(-1.725,0) 4(-1.725,-0.5) 5(-1.725,-1) 11(1.725,-1) 12(1.725,-0.5) 13(1.725,0) 14(1.725,0.5) 15(1.725,1)
  rect 0.28x0.85 smd: 6(-1,-1.725) 7(-0.5,-1.725) 8(0,-1.725) 9(0.5,-1.725) 10(1,-1.725) 16(1,1.725) 17(0.5,1.725) 18(0,1.725) 19(-0.5,1.725) 20(-1,1.725)
  rect 2.05x2.05 smd: 21(0,0)

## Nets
5.0V: C63.1 C64.2 F1.2 FB2.2 Q1.1(S1) Q1.2(S2) Q1.3(S3)
5.0V_IN: D5.4 F1.1 J14.1 Q1.5(D5) Q1.6(D6) Q1.7(D7) Q1.8(D8) TP2.1(TP) U7.5(VIN)
5VIN: C57.1 C65.1 C66.1 C67.2 C68.1 C75.1 C76.2 C77.1 C82.1 C83.2 C84.1 FB1.2 FB2.1 R76.1 R77.1 R78.1 U8.3(VIN) U10.5(EN) U10.8(IN) U11.2(IN) U13.5(V+)
+1.2V: C98.1 R87.1 R90.1 U2.9(VOCM)
+1.8V: C24.1 C28.1 C69.2 C72.1 C81.1 FB6.2 R81.1 R87.2 R88.2 TP13.1(TP) U9.1(OUT1) U9.2(SENSE) U9.19(OUT2) U9.20(OUT3) U13.3(VIN+)
+2.1V: C23.1 C70.1 L10.1 U8.6(FB) U9.14(EN) U9.15(IN1) U9.16(IN2) U9.17(IN3)
+4.7V: C16.1 C17.1 C18.1 C19.1 C51.1 C55.1 C71.1 C94.1 C95.1 C96.1 C97.1 D1.2 D2.2 D3.2 D6.2 D7.2 FB4.1 TP5.1(TP) U1.7(+VS) U2.5(VS+#5) U2.6(VS+#6) U2.7(VS+#7) U2.8(VS+#8) U2.12(\\P\D\) U3.3(\\P\D\) U3.10(VS+) U4.3(\\P\D\) U4.10(VS+)
-4.7V: C14.1 C15.1 D1.1 FB5.1 TP7.1(TP) U1.4(-VS)
-5V: C86.1 C90.1 U11.1(OUT) U12.5(EN) U12.8(IN)
A1.8V: FB3.2 FB7.2 R88.1 U13.4(VIN-)
AVDD1.8V: C30.1 C31.1 C32.1 C33.1 C34.1 C35.1 C36.1 C37.1 C38.1 C39.1 C40.1 C41.1 C42.1 FB7.1 TP11.1(TP) U5.6(AVDD#6) U5.7(AVDD#7) U5.10(AVDD#10) U5.11(AVDD#11) U5.14(AVDD#14) U5.15(AVDD#15) U5.20(AVDD#20) U5.23(AVDD#23) U5.28(AVDD#28) U5.29(AVDD#29) U5.32(AVDD#32) U5.33(AVDD#33) U5.36(AVDD#36)
DVDD1.8V: C43.1 C44.1 C45.1 C46.1 FB3.1 JP2.1(PIN1) R56.1 R57.1 TP12.1(TP) U5.5(DVDD#5) U5.38(DVDD#38) U5.47(DVDD#47) U5.52(DVDD#52)
GND: C3.1 C4.1 C5.1 C6.1 C11.2 C14.2 C15.2 C16.2 C17.2 C18.2 C19.2 C22.2 C23.2 C27.2 C28.2 C29.2 C30.2 C31.2 C32.2 C33.2 C34.2 C35.2 C36.2 C37.2 C38.2 C39.2 C40.2 C41.2 C42.2 C43.2 C44.2 C45.2 C46.2 C47.2 C48.2 C50.2 C51.2 C52.2 C54.2 C55.2 C56.2 C57.2 C58.2 C59.2 C60.2 C61.2 C62.2 C63.2 C64.1 C65.2 C66.2 C67.1 C68.2 C69.1 C70.2 C71.2 C72.2 C75.2 C76.1 C77.2 C78.2 C80.2 C81.2 C82.2 C83.1 C84.2 C86.2 C87.2 C89.2 C90.2 C94.2 C95.2 C96.2 C97.2 C98.2 C103.2 C104.2 D2.1 D3.1 D4.2(CATHODE) D5.1 D5.2 D5.3 D6.1 D7.1 J1.2(SHIELD2) J1.3(SHIELD3) J1.4(SHIELD4) J1.5(SHIELD1) J2.2(SHIELD2) J2.3(SHIELD3) J2.4(SHIELD4) J2.5(SHIELD1) J3.2(SHIELD2) J3.3(SHIELD3) J3.4(SHIELD4) J3.5(SHIELD1) J4.2(SHIELD2) J4.3(SHIELD3) J4.4(SHIELD4) J4.5(SHIELD1) J5.2(SHIELD2) J5.3(SHIELD3) J5.4(SHIELD4) J5.5(SHIELD1) J6.2(SHIELD2) J6.3(SHIELD3) J6.4(SHIELD4) J6.5(SHIELD1) J7.2(SHIELD2) J7.3(SHIELD3) J7.4(SHIELD4) J7.5(SHIELD1) J8.2(GND#2) J8.3(GND#3) J8.4(GND#4) J8.5(GND#5) J10.2(GND#2) J10.3(GND#3) J10.4(GND#4) J10.5(GND#5) J12.5 J12.6 J12.11 J12.12 J12.17 J12.18 J12.23 J12.24 J12.29 J12.30 J12.35 J12.36 J12.41 J12.42 J12.47 J12.48 J12.53 J12.54 J12.59 J12.60 J12.61 J12.62 J12.67 J12.68 J12.73 J12.74 J12.79 J12.80 J12.85 J12.86 J12.91 J12.92 J12.97 J12.98 J12.103 J12.104 J12.109 J12.110 J12.116 J12.121(GND#121) J12.122(GND#122) J12.123(GND#123) J12.124(GND#124) J12.125(GND#125) J12.126(GND#126) J12.127(GND#127) J12.128(GND#128) J13.5(GND) J13.6(GND1) J13.7(GND2) J13.8(GND3) J13.9(GND4) J14.2 J14.3 JP2.3(PIN3) JP7.1(PIN1) JP8.1(PIN1) R7.2 R12.2 R25.1 R28.2 R30.1 R31.2 R32.1 R35.1 R38.2 R44.2 R48.2 R54.2 R58.2 R59.2 R63.2 R74.2 R79.2 R80.2 R82.2 R84.2 R86.2 R90.2 T3.3(PRIMARY_DOT) T4.3(PRIMARY_DOT) TP3.1(TP) TP6.1(TP) TP8.1(TP) TP9.1(TP) TP10.1(TP) TP14.1(TP) U2.13(VS-#13) U2.14(VS-#14) U2.15(VS-#15) U2.16(VS-#16) U2.17(PWRPAD) U3.5(VS-) U4.5(VS-) U5.57(POWERPAD) U6.7(GND#7) U6.18(GND#18) U6.21(GND#21) U6.25(AGND) U6.26(TEST) U7.2(GND) U8.4(GND) U9.7(200MV) U9.8(GND#8) U9.10(800MV) U9.18(GND#18) U9.21(PWRPAD) U10.4(GND) U10.9(TPAD) U11.4(GND) U12.4(GND) U12.9(TPAD) U13.2(GND)
P4.7V: C78.1 C79.1 FB4.2 R83.1 U10.1(OUT)
VIN-: R16.1 R28.1 U1.2(INV-IN)
A_INM: J2.1(CENTER) R9.1
A_INP: J1.1(CENTER) R4.1
AI_NM: T1.6(PRIMARY_DOT) T2.4(PRIMARY)
AI_NP: T1.4(PRIMARY) T2.6(PRIMARY_DOT)
AIN+: C1.1 T2.1(SECONDARY_DOT)
AIN-: C7.1 T2.3(SECONDARY)
AINM: R91.2 U5.8(INAM)
AINM_M: L3.1 R10.2 R13.2 R14.1
AINMM_M: R11.2 R14.2 R15.1
AINP: R50.2 U5.9(INAP)
AINP_P: L1.1 R1.2 R2.1 R6.1
AINPP_P: R2.2 R3.1 R5.1
B+: R20.1 U2.10(OUT+)
B-: R33.1 U2.11(OUT-)
B_INM: J5.1(CENTER) R41.1 R42.1 R44.1
B_INP: J4.1(CENTER) R38.1 R40.1
BI_NM: C20.2 L7.1 R43.2
BI_NP: C20.1 L6.1 R39.2
BIN+: C101.2 D2.3 R36.1 R40.2 U3.4(IN+)
BIN-: C100.2 D6.3 R37.1 R42.2 U3.6(IN-)
BIN_+: C100.1 R37.2 R39.1 U3.9(OUT+)
BIN_-: C101.1 R36.2 R43.1 U3.1(OUT-)
BINM: R23.2 U5.13(INBM)
BINP: R26.2 U5.12(INBP)
C_INM: J7.1(CENTER) R52.1 R54.1 R92.1
C_INP: J6.1(CENTER) R48.1 R51.1
CI_NM: C25.2 L9.1 R53.2
CI_NP: C25.1 L8.1 R49.2
CIN+: C102.2 D3.3 R46.1 R51.2 U4.4(IN+)
CIN-: C99.2 D7.3 R47.1 R52.2 U4.6(IN-)
CIN_+: C99.1 R47.2 R49.1 U4.9(OUT+)
CIN_-: C102.1 R46.2 R53.1 U4.1(OUT-)
CINM: R34.2 U5.30(INCM)
CINP: R21.2 U5.31(INCP)
CLK_INP: C49.1 R59.1 T3.1(PRIMARY)
CLKINM: R61.1 T3.4(SECONDARY) U5.22(CLKM)
CLKINP: R60.2 T3.6(SECONDARY_DOT) U5.21(CLKP)
CLOCK_IN: C49.2 J8.1(CENTER)
D_INP: J3.1(CENTER) JP1.1 R22.1 R32.2
DA0M: J12.32 U5.4(DA0M)
DA0P: J12.34 U5.3(DA0P)
DA1M: J12.38 U5.2(DA1M)
DA1P: J12.40 U5.1(DA1P)
DAVP: D1.3 R22.2 R89.1
DB0M: J12.44 U5.56(DB0M)
DB0P: J12.46 U5.55(DB0P)
DB1M: J12.50 U5.54(DB1M)
DB1P: J12.52 U5.53(DB1P)
DBIN+: L4.1 R20.2
DBIN-: L5.1 R33.2
DBIN_M: C12.2 L5.2 R34.1 R35.2
DBIN_P: C12.1 L4.2 R21.1 R25.2
DC0M: J12.70 U5.46(DC0M)
DC0P: J12.72 U5.45(DC0P)
DC1M: J12.76 U5.44(DC1M)
DC1P: J12.78 U5.43(DC1P)
DCLKM: J12.56 U5.51(DCLKM)
DCLKP: J12.58 U5.50(DCLKP)
DD0M: J12.82 U5.42(DD0M)
DD0P: J12.84 U5.41(DD0P)
DD1M: J12.88 U5.40(DD1M)
DD1P: J12.90 U5.39(DD1P)
DIN_P: C11.1 R89.2 U1.3(NON-IN)
DINM: R3.2 U5.35(INDM)
DINP: R15.2 U5.34(INDP)
FCLKM: J12.64 U5.49(FCLKM)
FCLKP: J12.66 U5.48(FCLKP)
FPGA_CSEL: J12.115 R70.1
FPGA_SCLK: J12.119 R67.1
FPGA_SDI: J12.117 R68.1
FPGA_SDO: J12.113 R69.1
FTDI_VCCIO1.8V: FB6.1 U6.4(VCCIO)
IN+: C10.1 C13.2 R27.2 U2.2(IN+)
IN-: C8.1 C13.1 R19.2 U2.3(IN-)
INM: C9.2 R27.1 R29.1 R30.2
INP: C9.1 R17.1 R18.2 R19.1
N4.7V: C87.1 C88.1 FB5.2 R85.1 U12.1(OUT)
OUT+: R16.2 R18.1 U1.6(OUT)
PDN: JP2.2(PIN2) U5.37(PDN)
RESET: C47.1 R58.1 SW1.1 U5.24(RESET)
SCLK: JP3.2 R67.2 R71.1
SDATA: JP4.2 R68.2 R72.1
SDOUT: JP6.2 R69.2 R73.1
SEN: JP5.2 R70.2 R75.1
SYSREF_IN: C53.2 J10.1(CENTER)
SYSREFINP: C53.1 R63.1 T4.1(PRIMARY)
SYSREFM: R65.1 T4.6(SECONDARY_DOT) U5.26(SYSREFM)
SYSREFP: R64.2 T4.4(SECONDARY) U5.25(SYSREFP)
T1_M: R9.2 R12.1 T1.1(SECONDARY_DOT)
T1_P: R4.2 R7.1 T1.3(SECONDARY)
VCM: C4.2 C48.1 R8.2 R45.1 R55.1 TP1.1(TP) U5.27(VCM)
N18154317: JP3.1 U5.16(SCLK)
N18154318: JP4.1 U5.17(SDATA)
N18154319: JP6.1 U5.19(SDOUT)
N18154320: JP5.1 R56.2 U5.18(SEN)
N18158256: C58.1 C59.1 FB1.1 U6.20(VCC)
N18158298: R73.2 U6.3(D2)
N18158304: R71.2 U6.1(D0)
N18158332: C61.1 J13.2(D-) U6.16(USBDM)
N18158362: C62.1 U6.17(3V3OUT)
N18158372: C60.1 J13.3(D+) U6.15(USBDP)
N18158488: R72.2 U6.5(D1)
N18185709: Q1.4(G) U7.4(GATE)
N18185817: D4.1(ANODE) R76.2
N18186847: R75.2 U6.11(D3)
N18187243: J13.4(ID) R74.1
N18187932: R57.2 SW1.2
N18195117: C50.1 R60.1 R61.2
N18195272: C52.1 T3.2(PRIMARY_CT) T3.5(SECONDARY_CT)
N18195497: C54.1 R64.1 R65.2
N18195560: C56.1 T4.2(PRIMARY_CT) T4.5(SECONDARY_CT)
N18310229: C5.2 T1.2(SECONDARY_CT) T1.5(NC)
N18310285: C3.2 R6.2 R8.1 R10.1
N18310303: C2.1 L2.2 R5.2
N18310305: C2.2 L2.1 R11.1
N18310412: C1.2 L1.2 R1.1
N18310438: C7.2 L3.2 R13.1
N18310637: C6.2 T2.2(SECONDARY_CT) T2.5(NC)
N18328495: C8.2 R17.2 U2.4(FB+)
N18328553: C10.2 R29.2 U2.1(FB-)
N18331866: JP1.2 R31.1
N18332861: C21.1 L6.2 R23.1 R24.2
N18332866: C21.2 L7.2 R24.1 R26.1
N18333057: C22.1 R45.2 U3.7(VOCM)
N18344049: C26.1 L8.2 R50.1 R62.2
N18344053: C26.2 L9.2 R62.1 R91.1
N18344107: C27.1 R55.2 U4.7(VOCM)
N18356381: C80.1 U10.6(NR/SS)
N18356397: C79.2 R83.2 R84.1 U10.2(FB)
N18358821: C91.1 U11.5(CFLY+)
N18358826: C91.2 U11.3(CFLY-)
N18359253: C89.1 U12.6(NR/SS)
N18359269: C88.2 R85.2 R86.1 U12.2(FB)
N18364475: R82.1 TP4.1(TP) U13.1(OUT)
N18386721: L10.2 U8.2(SW)
N18386761: C24.2 U9.3(FB)
N18386804: R81.2 U9.4(PG)
N18386812: C29.1 U9.13(NR/SS)
N18386907: R77.2 R79.1 U8.5(EN)
N18386909: R78.2 R80.1 U8.1(MODE)
N18422421: JP7.2(PIN2) R41.2
N18422424: C103.1 JP7.3(PIN3)
N18424509: JP8.2(PIN2) R92.2
N18424511: C104.1 JP8.3(PIN3)

Pads without a net: J12 1 2 3 4 7 8 9 10 13 14 15 16 19 20 21 22 25 26 27 28 31 33 37 39 43 45 49 51 55 57 63 65 69 71 75 77 81 83 87 89 93 94 95 96 99 100 101 102 105 106 107 108 111 112 114 118 120; J13 1; NOREF 1; NOREF#5 1; NOREF#6 1; NOREF#8 1; NOREF#27 1; NOREF#28 1; NOREF#37 1; NOREF#38 1; NOREF#39 1; NOREF#40 1; U1 1 5 8; U3 2 8; U4 2 8; U6 2 6 8 9 10 12 13 14 19 22 23 24 27 28; U7 1 3; U9 5 6 9 11 12; U10 3 7; U12 3 7

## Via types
v1: diameter 0.508, hole 0.254, TOP to BOTTOM, 2057 vias
v2: diameter 0.4, hole 0.203, TOP to BOTTOM, 41 vias
v3: diameter 0.559, hole 0.305, TOP to BOTTOM, 273 vias

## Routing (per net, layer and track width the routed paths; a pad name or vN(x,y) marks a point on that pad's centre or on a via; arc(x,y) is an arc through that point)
5.0V:
  vias: v1(21.26,18.54) v1(21.89,20.57) v1(21.89,19.43) v1(22.28,21.34) v1(22.28,18.54) v1(23.42,21.34) v1(23.42,18.54) v1(23.93,17.53) v1(24.05,20.57) v1(24.05,19.43) v1(24.56,21.34) v1(24.56,18.67) v1(25.32,24.38) v1(25.32,22.99) v1(25.45,18.67) v1(25.7,21.34) v1(26.47,24.89) v1(26.47,23.62) v1(26.47,22.61) v1(26.47,18.67) v1(26.59,21.21) v1(26.59,20.07)
5.0V_IN: length 72.1
  TOP w0.254: v3(22.03,22.31) v3(21.03,22.31) ; v3(22.03,22.31) v3(22.03,23.31) ; v3(22.03,22.31) v3(23.03,22.31) v3(23.03,23.31) ; v3(21.03,22.31) 20.93,22.4 Q1.8 ; v3(21.03,22.31) v3(21.03,23.31) ; v3(23.03,24.31) v3(23.03,23.31) ; v3(23.03,24.31) v3(23.03,25.31) ; v3(23.03,24.31) 22.06,24.31 v3(22.05,24.3) ; v3(23.03,23.31) v3(22.03,23.31) ; v3(22.05,24.3) 22.05,25.29 v3(22.03,25.31) ; v3(22.05,24.3) 21.04,24.3 v3(21.03,24.31) ; v3(22.05,24.3) 22.03,24.28 v3(22.03,23.31) ; v3(21.03,26.31) 20.93,26.21 Q1.5 ; v3(21.03,26.31) v3(22.03,26.31) ; v3(21.03,26.31) v3(21.03,25.31) ; v3(22.03,26.31) v3(22.03,25.31) ; v3(22.03,26.31) v3(23.03,26.31) v3(23.03,25.31) ; v3(21.03,23.31) v3(21.03,24.31) ; v3(21.03,23.31) v3(22.03,23.31) ; v3(23.03,25.31) v3(22.03,25.31) ; v3(21.03,25.31) v3(22.03,25.31) ; v3(21.03,25.31) v3(21.03,24.31)
  TOP w0.711: J14.1 15.85,33.44 ; J14.1 15.85,29.32 ; J14.1 11.73,33.44 ; J14.1 11.73,29.32 ; TP2.1 17.42,21.3 ; TP2.1 17.42,18.58 ; TP2.1 14.69,18.58 ; TP2.1 14.69,21.3
  LYR3_PWR w0.711: J14.1 15.85,29.32 ; J14.1 11.73,29.32 ; J14.1 15.85,33.44 ; J14.1 11.73,33.44 ; TP2.1 17.42,18.58 ; TP2.1 14.69,21.3 ; TP2.1 14.69,18.58 ; TP2.1 17.42,21.3
  BOTTOM w0.711: J14.1 15.85,29.32 ; J14.1 11.73,29.32 ; J14.1 11.73,33.44
  vias: v1(8.05,27.56) v1(8.05,26.04) v1(8.05,24.13) v1(8.05,22.61) v1(8.05,21.08) v1(8.18,19.81) v1(8.18,18.29) v1(9.07,23.88) v1(9.07,21.72) v1(9.19,22.86) v1(9.32,18.16) v1(9.45,34.67) v1(10.08,23.5) v1(10.08,21.97) v1(10.46,33.4) v1(10.46,31.88) v1(10.46,30.99) v1(10.46,29.46) v1(10.85,18.16) v1(11.1,22.73) v1(11.23,34.67) v1(11.99,20.57) v1(11.99,19.05) v1(12.12,23.5) v1(12.12,21.97) v1(12.75,18.16) v1(13,19.81) v1(13.51,25.15) v1(13.51,23.62) v1(13.64,34.67) v1(13.64,28.19) v1(13.64,26.67) v1(13.64,22.23) v1(14.02,20.57) v1(14.02,19.05) v1(14.27,18.16) v1(14.53,24.38) v1(14.91,28.19) v1(14.91,26.67) v1(15.16,22.23) v1(15.42,34.67) v1(15.54,25.15) v1(15.54,23.62) v1(15.93,27.43) v1(16.56,34.8) v1(16.56,33.27) v1(16.69,25.02) v1(16.69,23.5) v1(16.94,28.19) v1(16.94,26.67) v1(16.94,22.35) v1(17.45,34.16) v1(17.45,32.64) v1(17.45,31.12) v1(17.45,29.59) v1(17.7,24.26) v1(17.83,28.7) v1(17.83,27.18) v1(18.08,25.78) v1(18.34,34.8) v1(18.34,33.27) v1(18.34,31.75) v1(18.47,30.35) v1(18.47,22.35) v1(18.47,21.34) v1(18.47,18.16) v1(18.72,25.02) v1(18.72,23.5) v1(18.85,27.94) v1(19.35,34.04) v1(19.35,32.51) v1(19.48,31.12) v1(19.48,29.59) v1(19.86,28.7) v1(19.86,27.18) v1(19.99,21.34) v1(19.99,18.16) v1(20.37,34.8) v1(20.37,33.27) v1(20.37,31.75) v1(21.77,34.8) v1(21.77,33.27) v1(21.77,31.75)
5VIN: length 19.1
  TOP w0.254: v1(25.25,46.1) 25.07,46.1 C68.1 ; v1(26.09,46.74) 26.47,47.12 U8.3 ; C83.2 v1(37.13,32.13)
  TOP w0.305: R77.1 v1(30.28,48.01)
  TOP w0.508: v1(99.49,39.37) C57.1 99.49,38.63 v1(98.83,38.63) ; v1(100.13,39.12) FB1.2 v1(101.02,40.26) ; U13.5 v1(42.26,50.33) ; R78.1 v1(23.62,46.99)
  BOTTOM w0.483: v1(40.56,39.88) 41.73,41.05 41.73,42.16 41.33,42.57 41.33,48.89 42.26,49.83 v1(42.26,50.33)
  vias: v1(27.99,21.59) v1(28.37,21.08) v1(29.39,21.59) v1(29.39,20.83) v1(29.39,19.56) v1(30.15,20.83) v1(31.04,20.83) v1(31.29,21.97) v1(31.29,19.94) v1(31.67,22.35) v1(31.8,21.21) v1(32.31,21.97) v1(32.31,20.7) v1(32.82,19.43) v1(32.94,21.21) v1(32.94,20.45) v1(33.07,21.97) v1(33.45,19.94) v1(35.23,32.39) v1(36.12,31.37) v1(38.28,32.13) v1(39.17,32.26) v1(39.42,36.2) v1(39.55,39.88) v1(39.55,33.53) v1(40.06,32.77) v1(40.18,36.2) v1(40.56,39.12) v1(40.56,37.08) v1(40.56,33.53) v1(40.56,32.13) v1(40.94,36.2) v1(41.07,32.77) v1(41.2,36.83) v1(41.58,33.53) v1(41.58,32.13) v1(41.71,36.07)
+1.2V: length 5
  TOP w0.203: v1(36.5,49.66) v1(37.39,49.66) 37.39,49.3 R87.1 ; R90.1 v1(36.25,47.62)
  TOP w0.305: U2.9 45.64,75.16
  TOP w0.483: C98.1 45.29,74.26 45.29,74.8 45.64,75.16
  vias: v1(43.18,72.06) v1(43.33,72.85) v1(43.99,72.24) v2(36.75,48.26) v2(37.01,50.04) v2(37.39,48.26)
+1.8V: length 14.1
  TOP w0.203: U9.2 U9.1 ; U9.19 U9.20
  BOTTOM w0.203: TP13.1 24.84,43.69 30.78,43.69 v1(31.29,43.18)
  vias: v1(31.17,45.59) v1(31.29,46.86) v1(31.42,47.5) v1(31.93,47.75) v1(31.93,46.99) v1(31.93,43.56) v1(32.56,43.18) v1(33.32,43.56) v1(33.83,43.18) v1(34.59,43.69) v1(35.1,43.18) v1(35.74,43.69) v1(36.37,45.59) v1(36.37,43.18) v1(38.4,45.59) v1(39.04,46.61) v1(39.04,45.59) v1(39.55,48.39) v1(40.44,46.48) v1(40.69,48.39)
+2.1V: length 2.7
  TOP w0.254: U9.14 U9.15
  TOP w0.305: v1(27.74,49.66) v1(27.35,49.27) U8.6 ; U9.17 U9.16
  vias: v1(27.86,52.7) v1(27.86,51.18) v1(27.99,49.02) v1(28.37,51.94) v1(28.88,52.7) v1(28.88,51.18) v1(29.13,49.15) v1(29.39,51.94) v1(29.64,50.17) v1(29.9,52.7) v1(30.02,51.56) v1(30.15,50.8) v1(30.78,52.7) v1(30.78,51.82) v1(30.91,50.42) v1(31.8,50.8) v1(31.93,51.44)
+4.7V: length 31.4
  TOP w0.254: v1(74.15,74.59) U3.10 75.14,75.58 75.34,75.58 75.38,75.62 75.61,75.62 75.65,75.58 75.76,75.58 U3.3 ; U4.3 79.45,64.57 79.37,64.65 79.37,64.7 79.2,64.87 79.15,64.87 79.01,65.01 U4.10 v1(77.61,65.01)
  TOP w0.305: 47.08,76.4 47.03,76.35 U2.12
  TOP w0.483: 47.08,76.4 C18.1 48.29,77.6 v1(48.81,78.12) ; C16.1 C17.1 39.66,88.78 v1(38.91,89.54) ; C16.1 37.64,86.74 36.96,86.76 U1.7 ; C16.1 38.05,87.1 v1(38.79,86.36) ; v1(26.37,99) 25.97,98.6 D1.2 ; D2.2 v1(80.14,75.98) ; D3.2 v1(82.82,61.75) ; D7.2 v1(81.53,68.34) ; D6.2 v1(74.57,79.72)
  TOP w0.711: TP5.1 32.4,40.1 ; TP5.1 29.68,40.1 ; TP5.1 32.4,37.37 ; TP5.1 29.68,37.37
  LYR3_PWR w0.711: 29.68,40.1 TP5.1 ; TP5.1 29.68,37.37 ; TP5.1 32.4,40.1
  vias: v1(28.12,42.42) v1(28.12,41.02) v1(28.12,39.88) v1(28.12,38.86) v1(28.12,37.85) v1(28.88,41.66) v1(28.88,40.51) v1(28.88,39.37) v1(28.88,38.48) v1(28.88,37.47) v1(29.39,42.42) v1(29.64,40.26) v1(29.77,41.15) v1(30.02,42.04) v1(32.44,41.91) v1(32.44,41.02) v1(32.56,40.26) v1(41.71,76.05) v1(41.96,75.29) v1(42.52,75.9)
-4.7V: length 18.8
  TOP w0.508: D1.1 v1(27.27,98.1)
  TOP w0.711: TP7.1 39.26,22.51 ; TP7.1 36.53,22.51 ; TP7.1 36.53,25.24 ; TP7.1 39.26,25.24
  LYR3_PWR w0.203: 34.59,21.46 32.82,23.24 32.82,23.5
  LYR3_PWR w0.711: TP7.1 39.26,25.24 ; TP7.1 36.53,22.51 ; TP7.1 36.53,25.24 ; TP7.1 39.26,22.51
  vias: v1(27.1,87.63) v1(27.36,85.47) v1(27.86,87) v1(28.37,86.36) v1(28.37,84.2) v1(28.5,85.34) v1(29.01,89.54) v1(29.51,85.34) v1(29.59,86.95) v1(29.77,88.77) v1(30.28,87.88) v1(30.53,86.36) v1(31.04,87.38) v1(31.17,88.65) v1(32.05,87.88) v1(36.35,22.48) v1(36.45,25.35) v1(36.63,21.84) v1(36.96,25.7) v1(37.26,21.84) v1(37.92,21.77) v1(38.53,21.84) v1(38.99,25.65) v1(39.04,22.35) v1(39.42,25.15) v1(39.42,21.84) v1(41.2,24) v1(41.2,22.99) v1(41.2,21.84)
-5V: length 4.1
  TOP w0.305: U12.5 v1(48.39,30.56)
  BOTTOM w0.305: v1(48.39,30.56) v1(45.09,30.56)
  vias: v1(37.64,30.99) v1(37.64,30.1) v1(38.28,30.1) v1(38.4,30.99) v1(40.31,30.99) v1(40.31,30.23) v1(42.6,30.99) v1(42.98,30.48) v1(43.48,30.99) v1(43.61,30.1) v1(43.99,30.61) v1(44.37,30.1) v1(44.5,30.99)
A1.8V:
  vias: v1(41.96,48.39) v1(42.85,48.01) v1(42.85,46.86) v1(43.23,48.89) v1(43.23,47.37) v1(43.48,51.94) v1(44.12,49.02) v1(44.5,51.94) v1(44.75,49.02) v1(45.14,51.31) v1(45.14,50.04) v1(45.14,48.01) v1(45.14,46.86)
AVDD1.8V: length 46.2
  TOP w0.203: U5.15 64.21,68.52 ; U5.11 64.96,66.27 ; U5.20 61.71,68.52 ; v1(57.18,68.52) 57.28,68.42 U5.28 ; U5.33 56.96,65.77 ; U5.7 64.96,64.27 ; U5.32 56.96,66.27 ; U5.36 56.96,64.27 ; v1(66.4,63.83) 66.33,63.77 65.58,63.77 ; U5.10 64.96,65.77 ; U5.23 60.21,68.52 ; U5.6 64.96,63.77 ; U5.29 56.96,67.77 ; U5.14 64.96,67.77
  TOP w0.254: 56.96,66.27 v1(55.6,66.27) ; 61.71,68.52 v1(61.71,69.4) ; v1(56.34,68.17) 56.74,67.77 56.96,67.77 ; 64.96,66.27 v1(66.02,66.27) ; 64.96,63.77 65.58,63.77 ; 56.96,65.77 v1(56.03,65.77) ; 64.96,64.27 v1(65.83,64.27) ; 60.21,68.52 v1(60.21,69.43) ; 64.96,65.77 v1(65.79,65.77) ; 56.96,64.27 v1(56.06,64.27) ; 64.96,67.77 v1(65.76,67.77) ; 64.21,68.52 v1(64.21,69.39)
  TOP w0.635: FB7.1 48.01,47.62 v1(48.82,47.62)
  TOP w0.711: TP11.1 47.64,46.07 ; TP11.1 44.92,43.34 ; TP11.1 47.64,43.34
  LYR3_PWR w0.711: TP11.1 47.64,46.07 ; TP11.1 44.92,43.34 ; TP11.1 47.64,43.34
  LYR4_PWR w0.711: 44.92,43.34 TP11.1 ; TP11.1 47.64,43.34 ; TP11.1 47.64,46.07 ; TP11.1 44.92,46.07
  BOTTOM w0.203: C41.1 65.07,65.28 ; C40.1 65.07,66.42 ; C38.1 65.07,64.14
  BOTTOM w0.508: v1(56.34,68.17) 56.69,67.82 56.95,67.82 ; v1(64.21,69.39) 63.68,68.86 C36.1 ; v1(57.18,68.52) 56.6,69.09 C33.1 ; v1(56.03,65.77) 56.26,65.53 56.95,65.53 ; v1(65.83,64.27) 65.7,64.14 65.07,64.14 ; v1(60.21,69.43) 60.25,69.39 C34.1 ; v1(56.06,64.27) 56.18,64.39 56.95,64.39 ; v1(55.6,66.27) 56.01,66.67 56.95,66.67 ; v1(65.76,67.77) 65.56,67.56 C42.1 ; v1(61.71,69.4) 61.65,69.34 C35.1 ; 65.07,66.42 65.86,66.42 v1(66.02,66.27) ; v1(65.79,65.77) 65.3,65.28 65.07,65.28 ; C37.1 v1(66.95,63.63)
  vias: v1(44.88,42.93) v1(45.9,42.55) v1(46.79,47.62) v1(47.04,48.39) v1(47.04,46.99) v1(47.17,42.55) v1(47.93,43.31) v1(48.31,46.1) v1(48.44,44.7) v1(48.56,42.55) v1(48.69,48.51) v1(48.69,46.86) v1(48.95,45.59) v1(48.95,43.31) v1(49.07,46.36) v1(49.07,44.07)
DVDD1.8V: length 69.4
  TOP w0.203: v1(62.21,59.64) U5.52 ; v1(59.71,59.63) U5.47 ; v1(65.83,63.27) U5.5
  TOP w0.254: U5.38 56.08,63.27 v1(56.06,63.3)
  TOP w0.508: FB3.1 47.88,51.87 v1(46.41,53.34)
  LYR3_PWR w0.711: JP2.1 94.87,42.49 ; JP2.1 94.87,40.31 ; JP2.1 92.68,40.31 ; JP2.1 92.68,42.49
  BOTTOM w0.203: v1(46.41,53.34) 45.01,53.34 40.69,57.66 22.28,57.66 17.58,52.96 17.58,47.37 TP12.1
  BOTTOM w0.508: 56.95,63.25 56.11,63.25 v1(56.06,63.3) ; v1(62.21,59.64) 62.28,59.72 C44.1 ; R57.1 v1(103.3,46.48) ; C43.1 65.56,62.99 v1(65.83,63.27) ; v1(59.71,59.63) 59.74,59.66 C45.1 ; R56.1 93.65,33.91 94.28,34.54 94.79,34.54 95.55,35.31 95.55,39.62 JP2.1
GND: length 690.3
  TOP w0.203: 62.23,42.88 62.18,42.82 v1(62.18,42.77) ; U3.5 75.91,76.35 v1(82.4,82.83) ; v1(58.62,55.78) 58.7,55.85 58.7,56.21 59.69,57.2 v1(59.69,57.28) v1(59.69,58.7) ; 33.46,49.15 v2(33.96,48.65) ; J2.3 v3(2.25,70.19) v3(2.25,69.32) ; 62.99,28.78 v1(63.02,28.75) ; 60.5,30.89 v1(60.4,30.78) ; v1(91.83,65.01) 80.91,65.01
  TOP w0.254: v1(27.74,46.74) 27.35,47.12 U8.4 ; 80.91,65.01 U4.5 ; v1(41.71,83.95) 41.29,83.53 R30.1 ; C11.2 v1(28.42,91.24)
  TOP w0.305: J12.103 v1(47.49,2.29) ; v1(102.03,34.92) 102.29,34.67 C58.2 ; J12.12 v1(75.5,10.84) ; J12.79 v1(53.49,2.29) ; J12.85 v1(51.99,2.24) ; J12.23 v1(72.5,2.31) ; v1(31.04,49.15) U9.18 U9.21 ; J12.59 v1(63.49,2.3) ; 33.46,49.15 U9.8 v1(35.86,49.15) ; J12.6 v1(77,10.86) ; J12.41 v1(67.99,2.28) ; J12.73 v1(55,2.27) ; J12.24 v1(72.5,10.82) ; J12.42 v1(67.99,10.82) ; v1(36.11,48.65) U9.7 v2(33.96,48.65) ; J12.104 v1(47.49,10.75) ; J12.18 v1(74,10.78) ; J12.109 v1(45.99,2.25) ; J12.47 v1(66.49,2.26) ; J12.48 v1(66.49,10.82) ; J12.92 v1(50.49,10.74) ; J12.68 v1(56.5,10.69) ; J12.54 v1(64.99,10.76) ; J12.110 v1(45.99,10.81) ; J12.97 v1(48.99,2.24) ; 30.28,49.15 v1(30.28,48.64) ; J12.11 v1(75.5,2.27) ; J12.67 v1(56.5,2.3) ; J12.74 v1(55,10.69) ; J12.86 v1(51.99,10.8) ; J12.116 v1(44.49,10.83) ; C57.2 99.49,37.06 ; C59.2 100.7,36.51 v1(100.51,36.7) ; J12.98 v1(48.99,10.79) ; J12.36 v1(69.49,10.87) ; J12.53 v1(64.99,2.25) ; J12.29 v1(71,2.26) ; R79.2 v1(30.15,46.86) ; J12.80 v1(53.49,10.72) ; J12.17 v1(74,2.23) ; v1(35.85,50.15) U9.10 34.72,50.15 34.72,50.14 34.32,50.14 33.95,49.78 v2(33.95,49.66) ; J12.60 v1(63.49,10.73) ; J12.61 v1(58,2.3) ; J12.91 v1(50.49,2.26) ; J12.62 v1(58,10.73) ; J12.5 v1(77,2.25) ; J12.35 v1(69.49,2.29) ; J12.30 v1(71,10.82)
  TOP w0.381: R38.2 v1(82.01,79.03) ; R90.2 38.53,47.62 37.52,46.61 C69.1 ; R48.2 v1(86.31,62.59) ; v1(32.82,44.7) 32.94,44.58 C28.2 33.71,45.09 v1(34.09,45.47) ; C69.1 v1(37.52,45.59) C81.2 ; C69.1 37.13,46.61 v1(37.13,46.74) ; R82.2 v1(36.88,50.8) ; v1(17.18,60.83) 17.12,60.89 R7.2 ; R12.2 17.12,69.23 v1(17.14,69.26) ; D3.1 v1(81.53,61.75) ; D2.1 v1(79.22,75.06)
  TOP w0.508: v1(117.54,35.89) 119.47,35.89 ; 119.47,35.89 v1(119.47,37.28) ; 119.47,35.89 J13.9 v1(121.2,35.89) ; 119.47,35.89 v1(119.47,34.38) ; D7.1 v1(82.82,68.34) ; C60.2 v1(109.6,42.16) ; v1(113.97,43.28) 113.97,44.79 ; 113.97,44.79 v1(113.97,46.18) ; 113.97,44.79 J13.7 v1(115.7,44.79) ; 113.97,44.79 v1(112.04,44.79) ; 113.97,35.89 J13.8 v1(115.7,35.89) ; 113.97,35.89 v1(112.04,35.89) ; 113.97,35.89 v1(113.97,37.28) ; 113.97,35.89 v1(113.97,34.38) ; 99.49,37.06 v1(99.49,36.45) ; U6.21 v1(102.86,33.85) ; C4.1 v1(44.86,66.88) ; R25.1 v1(48.44,70.23) ; D6.1 v1(75.48,80.63) ; v1(117.54,44.79) 119.47,44.79 ; 119.47,44.79 v1(119.47,46.18) ; 119.47,44.79 J13.6 v1(121.2,44.79) ; 119.47,44.79 v1(119.47,43.28) ; R59.2 v1(67.6,86.87) ; C50.2 v1(62.69,76.12) ; v1(115.41,41.94) J13.5 v1(112.75,41.94) ; U6.18 v1(104.81,33.79) ; C3.1 v1(42.06,65.13) ; C29.2 v1(33.45,54.74) ; C23.2 v1(30.91,54.23) ; C54.2 v1(57.61,76.15) ; v1(105.71,36.45) 105.71,35.94 ; R35.1 v1(51.87,73.66) ; U6.7 v1(102.21,27.12) ; R54.2 v1(86.31,67.43) ; 55.65,81.94 v1(55.12,81.94) ; C72.2 v1(43.1,43.69) ; U6.26 v1(99.61,33.78) ; R80.2 v1(24.31,49.02) ; R74.2 v1(109.65,44.3) ; U6.25 v1(100.26,31) ; R44.2 v1(78.59,82.45) ; C61.2 v1(109.58,37.8)
  TOP w0.635: v1(23.67,89.41) 24.58,88.5 C15.2 24.62,88.45 v1(23.8,87.63) ; C67.1 30.4,23.62 ; C14.2 26.3,90.21 v1(25.45,91.06) ; C87.2 40.82,26.16 v3(41.07,26.42) ; C16.2 v1(40.92,84.27) ; R28.2 v1(32.68,95.71) ; C17.2 v1(42.59,85.8)
  TOP w0.711: JP7.1 74.28,86.87 ; JP7.1 74.28,82.7 ; JP7.1 76.36,84.79 ; JP7.1 72.2,84.79 ; J10.4 58.99,101.61 ; J10.4 56.17,98.8 ; J10.4 58.99,98.8 ; 57.58,105.28 58.99,106.69 ; 57.58,105.28 58.99,103.88 ; 57.58,105.28 56.17,106.69 ; 67.2,92.45 68.61,93.85 ; 68.61,93.85 70.02,92.45 ; 68.61,93.85 70.02,95.26 ; 62.12,97.53 J8.5 ; J8.5 62.12,100.34 ; J8.5 64.94,100.34 ; JP2.3 94.87,35.23 ; JP2.3 92.68,35.23 ; JP2.3 92.68,37.41 ; JP2.3 94.87,37.41 ; 62.12,95.26 63.53,93.85 ; 63.53,93.85 64.94,92.45 ; 63.53,93.85 62.12,92.45 ; 51.09,101.61 J10.5 ; J10.5 53.91,98.8 ; J10.5 51.09,98.8 ; J8.2 70.02,97.53 ; J8.2 67.2,100.34 ; J8.2 70.02,100.34 ; 5.66,33.26 J14.2 5.66,29.5 ; TP14.1 115.44,26.24 ; TP14.1 115.44,24.05 ; TP14.1 113.26,26.24 ; TP14.1 113.26,24.05 ; JP8.1 86.39,70.65 ; JP8.1 83.44,73.6 ; JP8.1 83.44,70.65 ; JP8.1 86.39,73.6 ; 32.26,34.21 TP8.1 30.07,34.21 ; 34.77,54.69 TP6.1 ; TP6.1 36.96,52.5 ; TP6.1 36.96,54.69 ; TP6.1 34.77,52.5 ; TP10.1 71.88,107.39 ; TP10.1 69.7,105.21 ; TP10.1 71.88,105.21 ; TP10.1 69.7,107.39 ; 51.09,103.88 52.5,105.28 ; 52.5,105.28 53.91,106.69 ; 52.5,105.28 51.09,106.69 ; TP9.1 35.31,25.1 ; TP9.1 33.12,25.1 ; TP9.1 35.31,22.91
  LYR2_GND w0.711: JP8.1 86.01,71.03 ; JP8.1 83.82,73.22 ; JP8.1 83.82,71.03 ; JP8.1 86.01,73.22 ; 62.12,92.45 63.53,93.85 ; 63.53,93.85 64.94,92.45 ; 63.53,93.85 62.12,95.26 ; TP8.1 32.26,34.21 ; TP8.1 30.07,36.4 ; TP8.1 30.07,34.21 ; TP8.1 32.26,36.4 ; 51.09,106.69 52.5,105.28 ; 52.5,105.28 53.91,106.69 ; 52.5,105.28 51.09,103.88 ; 51.09,101.61 J10.5 ; J10.5 51.09,98.8 ; J10.5 53.91,98.8 ; J8.2 70.02,97.53 ; J8.2 70.02,100.34 ; J8.2 67.2,100.34 ; TP9.1 35.31,25.1 ; TP9.1 35.31,22.91 ; TP9.1 33.12,22.91 ; TP9.1 33.12,25.1 ; 62.12,97.53 J8.5 ; J8.5 62.12,100.34 ; J8.5 64.94,100.34 ; 56.17,106.69 57.58,105.28 ; 57.58,105.28 58.99,106.69 ; 57.58,105.28 58.99,103.88 ; 73.19,85.88 JP7.1 ; JP7.1 73.19,83.7 ; JP7.1 75.37,83.7 ; 113.26,26.24 TP14.1 ; TP14.1 115.44,26.24 ; TP14.1 115.44,24.05 ; TP14.1 113.26,24.05 ; TP10.1 71.88,105.21 ; TP10.1 69.7,105.21 ; TP10.1 69.7,107.39 ; TP10.1 71.88,107.39 ; 5.66,29.5 J14.2 ; J14.2 9.43,33.26 ; J14.2 5.66,33.26 ; J14.2 9.43,29.5 ; J14.3 12.68,28.46 ; J14.3 12.68,24.7 ; J14.3 8.91,28.46 ; J14.3 8.91,24.7 ; 92.68,35.23 JP2.3 ; JP2.3 92.68,37.41 ; JP2.3 94.87,37.41 ; JP2.3 94.87,35.23 ; 9.37,21.03 TP3.1 8.99,19.94 ; 56.17,98.8 J10.4 ; J10.4 58.99,101.61 ; J10.4 58.99,98.8 ; TP6.1 36.96,52.5 ; TP6.1 34.77,52.5 ; TP6.1 34.77,54.69 ; TP6.1 36.96,54.69 ; 68.61,93.85 70.02,92.45 ; 68.61,93.85 70.02,95.26 ; 68.61,93.85 67.2,92.45
  LYR4_PWR w0.711: 69.7,107.39 TP10.1 ; TP10.1 71.88,105.21 ; TP10.1 69.7,105.21 ; TP10.1 71.88,107.39 ; 68.61,93.85 70.02,92.45 ; 68.61,93.85 67.2,92.45 ; 68.61,93.85 70.02,95.26 ; 62.12,95.26 63.53,93.85 ; 63.53,93.85 62.12,92.45 ; 63.53,93.85 64.94,92.45 ; 73.19,83.7 JP7.1 ; JP7.1 75.37,83.7 ; JP7.1 73.19,85.88 ; 52.5,105.28 53.91,106.69 ; 52.5,105.28 51.09,106.69 ; 52.5,105.28 51.09,103.88 ; 57.58,105.28 58.99,106.69 ; 57.58,105.28 56.17,106.69 ; 57.58,105.28 58.99,103.88 ; 83.82,73.22 JP8.1 ; JP8.1 86.01,71.03 ; JP8.1 86.01,73.22 ; JP8.1 83.82,71.03 ; 62.12,97.53 J8.5 ; J8.5 64.94,100.34 ; J8.5 62.12,100.34 ; J10.5 53.91,98.8 ; J10.5 51.09,98.8 ; J10.5 51.09,101.61 ; J10.4 58.99,98.8 ; J10.4 56.17,98.8 ; J10.4 58.99,101.61 ; J8.2 70.02,100.34 ; J8.2 67.2,100.34 ; J8.2 70.02,97.53
  LYR5_GND w0.711: 73.19,83.7 JP7.1 ; JP7.1 75.37,83.7 ; JP7.1 73.19,85.88 ; TP8.1 32.26,34.21 ; TP8.1 32.26,36.4 ; TP8.1 30.07,34.21 ; TP8.1 30.07,36.4 ; 33.12,22.91 TP9.1 ; TP9.1 35.31,25.1 ; TP9.1 35.31,22.91 ; TP9.1 33.12,25.1 ; J14.2 9.43,33.26 ; J14.2 5.66,33.26 ; J14.2 5.66,29.5 ; J14.2 9.43,29.5 ; 8.99,19.94 TP3.1 9.37,21.03 ; 57.58,105.28 58.99,103.88 ; 57.58,105.28 58.99,106.69 ; 57.58,105.28 56.17,106.69 ; 92.68,35.23 JP2.3 ; JP2.3 94.87,37.41 ; JP2.3 94.87,35.23 ; JP2.3 92.68,37.41 ; 8.91,28.46 J14.3 ; J14.3 12.68,24.7 ; J14.3 8.91,24.7 ; J14.3 12.68,28.46 ; TP6.1 36.96,54.69 ; TP6.1 36.96,52.5 ; TP6.1 34.77,52.5 ; TP6.1 34.77,54.69 ; TP14.1 115.44,24.05 ; TP14.1 113.26,24.05 ; TP14.1 115.44,26.24 ; TP14.1 113.26,26.24 ; 63.53,93.85 64.94,92.45 ; 63.53,93.85 62.12,95.26 ; 63.53,93.85 62.12,92.45 ; 69.7,105.21 TP10.1 ; TP10.1 71.88,105.21 ; TP10.1 71.88,107.39 ; TP10.1 69.7,107.39 ; 52.5,105.28 53.91,106.69 ; 52.5,105.28 51.09,103.88 ; 52.5,105.28 51.09,106.69 ; 62.12,97.53 J8.5 ; J8.5 64.94,100.34 ; J8.5 62.12,100.34 ; 51.09,101.61 J10.5 ; J10.5 51.09,98.8 ; J10.5 53.91,98.8 ; 68.61,93.85 70.02,95.26 ; 68.61,93.85 70.02,92.45 ; 68.61,93.85 67.2,92.45 ; J10.4 58.99,98.8 ; J10.4 58.99,101.61 ; J10.4 56.17,98.8 ; 83.82,71.03 JP8.1 ; JP8.1 83.82,73.22 ; JP8.1 86.01,73.22 ; JP8.1 86.01,71.03 ; 67.2,100.34 J8.2 ; J8.2 70.02,100.34 ; J8.2 70.02,97.53
  BOTTOM w0.203: 119.82,60.71 119.82,59.82
  BOTTOM w0.254: C97.2 85.27,65.28 ; 79.55,80.39 75.71,76.55 C94.2
  BOTTOM w0.508: D5.1 6.27,48.62 ; D5.1 5.47,50.36 ; D5.1 6.27,52.17 ; D5.1 7.02,50.36 ; R63.2 v1(56.62,87.05) ; C5.1 22.58,62.69 v1(22.81,62.46) ; 100.03,47.62 C47.2 v1(100.63,47.62) ; R58.2 v1(100.13,46.36) ; D5.3 12.15,50.36 ; D5.3 11.35,52.2 ; D5.3 11.35,48.54 ; D5.3 10.55,50.36 ; C33.2 55.55,68.38 ; C37.2 68.48,62.94 v1(68.49,62.93) ; C42.2 v1(64.95,69.16) ; C48.2 55.93,70.23
  BOTTOM w0.711: J8.5 64.94,100.34 ; J8.5 62.12,100.34 ; J8.5 62.12,97.53 ; J8.2 70.02,97.53 ; J8.2 67.2,100.34 ; J8.2 70.02,100.34 ; 33.12,25.1 TP9.1 ; TP9.1 35.31,22.91 ; TP9.1 35.31,25.1 ; TP9.1 33.12,22.91 ; 34.77,54.69 TP6.1 ; TP6.1 34.77,52.5 ; TP6.1 36.96,54.69 ; TP6.1 36.96,52.5 ; 52.5,105.28 53.91,106.69 ; 52.5,105.28 51.09,106.69 ; 52.5,105.28 51.09,103.88 ; JP8.1 86.39,70.65 ; JP8.1 83.44,70.65 ; JP8.1 83.44,73.6 ; JP8.1 86.39,73.6 ; TP14.1 115.44,26.24 ; TP14.1 115.44,24.05 ; TP14.1 113.26,26.24 ; TP14.1 113.26,24.05 ; 62.12,92.45 63.53,93.85 ; 63.53,93.85 64.94,92.45 ; 63.53,93.85 62.12,95.26 ; TP10.1 71.88,105.21 ; TP10.1 69.7,105.21 ; TP10.1 71.88,107.39 ; TP10.1 69.7,107.39 ; 67.2,92.45 68.61,93.85 ; 68.61,93.85 70.02,95.26 ; 68.61,93.85 70.02,92.45 ; 92.35,36.93 JP2.3 92.68,37.41 ; 56.17,106.69 57.58,105.28 ; 57.58,105.28 58.99,103.88 ; 57.58,105.28 58.99,106.69 ; 74.28,82.7 JP7.1 ; JP7.1 76.36,84.79 ; JP7.1 74.28,86.87 ; JP7.1 72.2,84.79 ; 30.07,34.21 TP8.1 ; TP8.1 32.26,34.21 ; TP8.1 32.26,36.4 ; TP8.1 30.07,36.4 ; 51.09,98.8 J10.5 ; J10.5 51.09,101.61 ; J10.5 53.91,98.8 ; 8.99,19.94 TP3.1 9.37,21.03 ; J10.4 58.99,101.61 ; J10.4 56.17,98.8 ; J10.4 58.99,98.8
  vias: v1(0.74,95.61) v1(0.71,92.84) v1(0.69,82.17) v1(0.69,29.59) v1(0.69,25.78) v1(0.69,22.99) v1(0.69,20.19) v1(0.84,77.86) v1(0.81,52.45) v1(0.81,48.64) v1(0.81,44.83) v1(0.81,41.02) v1(0.81,37.21) v1(0.81,33.4) v1(0.86,80.62) v1(0.99,68.43) v1(0.99,66.53) v1(0.96,63.76) v1(0.99,61.83) v1(1.96,94.23) v1(2.08,79.25) v1(2.13,28.81) v1(2.11,26.04) v1(2.21,65.15) v1(2.67,21.34) v1(2.77,36.3) v1(2.74,33.53) v1(2.77,24.11) v1(3.15,95.53) v1(3.25,92.84) v1(3.28,80.55) v1(3.38,77.86) v1(3.4,66.45) v1(3.35,27.43) v1(3.5,63.76) v1(3.73,92.2) v1(3.86,61.83) v1(4.01,68.25) v1(3.99,22.73) v1(4.55,28.73) v1(4.71,55.94) v1(4.65,26.04) v1(4.8,99.93) v1(4.77,97.16) v1(4.8,70.16) v1(4.82,59.92) v1(4.98,75.34) v1(5.05,76.69) v1(5.18,73.54) v1(5.18,24.03) v1(5.28,33.53) v1(5.28,21.34) v1(5.64,94.11) v1(5.75,56.78) v1(5.84,60.96) v1(6.02,98.55) v1(5.94,72.67) v1(6.02,68.89) v1(5.94,66.45) v1(6.04,63.76) v1(6.25,57.36) v1(6.93,62.06) v1(6.98,71.68) v1(7.09,77.58) v1(7.06,74.81) v1(7.21,99.85) v1(7.21,58.12) v1(7.31,97.16) v1(7.34,67.54) v1(7.72,70.97) v1(7.68,56.32) v1(7.8,91.44) v1(7.8,83.82) v1(7.8,13.46) v1(7.92,96.39) v1(8.03,59.19) v1(8.31,76.2) v1(8.48,66.45) v1(8.48,16.87) v1(8.46,14.1) v1(8.63,69.98) v1(8.58,63.76) v1(8.99,103.74) v1(8.96,100.97) v1(9.19,60.13) v1(9.5,77.5) v1(9.6,74.81) v1(9.73,68.97) v1(10.21,102.36) v1(10.23,79.76) v1(10.26,82.53) v1(10.26,61.07) v1(10.39,87.86) v1(10.36,85.09) v1(10.62,66.3) v1(10.72,63.78) v1(10.9,16.79) v1(11.02,92.94) v1(11,90.17) v1(11,14.1) v1(11.4,103.66) v1(11.5,100.97) v1(11.48,81.15) v1(11.61,86.49) v1(11.58,61.07) v1(11.61,13.46) v1(12.24,91.57) v1(12.42,73.89) v1(12.39,71.12) v1(12.5,15.75) v1(12.55,68.92) v1(12.55,66.3) v1(12.67,82.45) v1(12.67,63.84) v1(12.8,87.79) v1(12.77,79.76) v1(12.9,85.09) v1(13.18,61.09) v1(13.31,97.9) v1(13.28,95.13) v1(13.44,92.87) v1(13.54,90.17) v1(13.64,72.52) v1(14.53,96.52) v1(14.58,78.97) v1(14.55,76.2) v1(14.58,68.94) v1(14.58,66.32) v1(14.73,63.81) v1(14.83,73.82) v1(14.93,71.12) v1(15.06,36.2) v1(15.29,61.32) v1(15.42,15.24) v1(15.42,13.46) v1(15.67,104.39) v1(15.72,97.82) v1(15.82,95.13) v1(15.82,82.05) v1(15.8,77.6) v1(15.85,84.82) v1(16.31,37.59) v1(16.56,103.51) v1(16.61,66.43) v1(16.59,63.73) v1(16.99,78.9) v1(17.07,102.36) v1(17.07,83.44) v1(17.09,76.2) v1(17.5,91.42) v1(17.47,88.65) v1(17.58,106.17) v1(17.6,36.2) v1(17.96,101.47) v1(18.26,84.74) v1(18.34,105.41) v1(18.36,82.05) v1(18.62,66.2) v1(18.72,90.04) v1(18.72,61.14) v1(18.77,63.94) v1(19.02,113.14) v1(19,110.37) v1(18.97,69.09) v1(19.23,100.84) v1(19.23,13.46) v1(19.4,96.12) v1(19.38,93.35) v1(19.91,91.34) v1(20.01,88.65) v1(20.12,99.57) v1(20.24,111.76) v1(20.62,94.74) v1(20.8,74.15) v1(20.78,71.38) v1(21.26,102.87) v1(21.26,98.43) v1(21.31,79.48) v1(21.28,76.71) v1(21.44,113.06) v1(21.51,61.14) v1(21.54,110.37) v1(21.56,84.94) v1(21.54,82.17) v1(21.64,68.99) v1(21.82,96.04) v1(21.92,93.35) v1(22.02,72.77) v1(22.28,99.44) v1(22.4,101.85) v1(22.53,78.11) v1(22.78,83.57) v1(22.78,67.44) v1(23.04,96.65) v1(23.21,74.07) v1(23.32,71.38) v1(23.5,44.7) v1(23.55,100.71) v1(23.55,11.05) v1(23.55,8.26) v1(23.55,5.46) v1(23.55,2.92) v1(23.55,0.76) v1(23.72,79.41) v1(23.8,96.27) v1(23.82,76.71) v1(23.77,37.82) v1(23.98,84.87) v1(23.98,69.09) v1(24.08,82.17) v1(24.05,15.11) v1(24.33,110.37) v1(24.36,113.14) v1(24.38,61.14) v1(24.69,95.38) v1(24.82,99.44) v1(25.07,94.49) v1(25.32,36.45) v1(25.37,106.91) v1(25.35,104.14) v1(25.35,43.05) v1(25.35,39.22) v1(25.58,111.76) v1(25.58,89.28) v1(25.58,10.16) v1(25.58,5.08) v1(25.93,41.35) v1(26.09,93.6) v1(26.59,105.54) v1(26.77,113.06) v1(26.82,69.07) v1(26.87,110.37) v1(26.92,66.25) v1(26.97,115.06) v1(26.97,63.96) v1(26.97,61.09) v1(27.13,75.82) v1(27.23,93.6) v1(27.23,91.06) v1(27.15,78.59) v1(27.36,92.33) v1(27.36,0.76) v1(27.61,96.77) v1(27.63,30.99) v1(27.66,33.76) v1(27.79,106.84) v1(27.89,104.14) v1(27.91,73.39) v1(27.89,70.62) v1(28.12,114.3) v1(28.12,17.78) v1(28.12,12.7) v1(28.12,7.62) v1(28.12,2.54) v1(28.37,95.89) v1(28.37,94.74) v1(28.37,77.22) v1(28.5,116.08) v1(28.5,61.09) v1(28.75,66.25) v1(28.93,69.12) v1(28.88,63.96) v1(28.88,32.39) v1(29.13,72.01) v1(29.39,17.91) v1(29.51,94.74) v1(29.56,78.52) v1(29.67,75.82) v1(29.92,98.3) v1(29.95,101.07) v1(30.07,33.69) v1(30.17,30.99) v1(30.33,73.31) v1(30.43,70.62) v1(30.53,93.73) v1(30.66,15.24) v1(30.66,10.16) v1(30.66,5.08) v1(31.17,99.7) v1(31.17,0.76) v1(31.47,83.42) v1(31.44,80.65) v1(31.6,106.79) v1(31.57,104.02) v1(31.67,112.06) v1(31.67,69.09) v1(31.72,61.12) v1(31.8,93.73) v1(31.8,54.99) v1(32.31,116.08) v1(32.36,101) v1(32.44,86.61) v1(32.46,98.3) v1(32.69,82.04) v1(32.69,18.16) v1(32.82,105.41) v1(32.82,53.85) v1(32.87,67.54) v1(32.89,62.36) v1(33.2,114.3) v1(33.2,109.22) v1(33.2,12.7) v1(33.2,7.62) v1(33.2,2.54) v1(33.45,85.6) v1(33.71,92.96) v1(33.88,83.34) v1(33.91,61.24) v1(34.01,106.71) v1(33.98,80.65) v1(34.01,73.26) v1(34.11,104.02) v1(34.52,77.96) v1(34.49,75.19) v1(34.52,69.02) v1(34.59,93.73) v1(34.62,17.78) v1(34.64,20.55) v1(34.98,84.71) v1(34.98,0.76) v1(35.23,71.88) v1(35.23,35.31) v1(35.61,94.74) v1(35.74,111.76) v1(35.74,76.58) v1(35.74,15.24) v1(35.74,10.16) v1(35.91,101.07) v1(35.89,98.3) v1(35.86,19.18) v1(36.12,116.08) v1(36.25,95.5) v1(36.42,73.18) v1(36.5,83.44) v1(36.52,70.49) v1(36.75,61.09) v1(36.88,91.82) v1(36.93,77.88) v1(37.01,96.27) v1(37.03,75.19) v1(37.13,99.7) v1(37.06,20.48) v1(37.16,68.99) v1(37.16,17.78) v1(37.39,66.29) v1(37.39,63.88) v1(37.57,105.9) v1(37.54,103.13) v1(37.64,81.92) v1(38.02,84.96) v1(38.15,92.96) v1(38.28,114.3) v1(38.28,109.22) v1(38.33,101) v1(38.33,72.88) v1(38.3,70.11) v1(38.33,61.24) v1(38.28,12.7) v1(38.28,7.62) v1(38.28,2.54) v1(38.43,98.3) v1(38.4,95.63) v1(38.56,78.82) v1(38.66,81.28) v1(38.79,104.52) v1(38.79,0.76) v1(38.91,76.71) v1(39.04,49.91) v1(39.29,68.92) v1(39.55,71.5) v1(39.93,116.08) v1(39.93,61.21) v1(39.98,105.82) v1(40.08,103.13) v1(40.06,87) v1(40.21,76.05) v1(40.23,66.38) v1(40.18,63.75) v1(40.34,74.65) v1(40.44,90.3) v1(40.49,73.2) v1(40.69,93.47) v1(40.82,111.76) v1(40.82,15.24) v1(40.82,10.16) v1(40.84,70.11) v1(41.07,91.69) v1(41.07,49.91) v1(41.33,6.48) v1(41.58,88.77) v1(41.76,71.91) v1(42.11,68.97) v1(42.09,61.21) v1(42.09,45.34) v1(42.26,99.8) v1(42.24,97.03) v1(42.3,6.48) v1(42.39,20.55) v1(42.37,17.78) v1(42.52,105.52) v1(42.49,102.75) v1(42.6,0.76) v1(42.85,84.96) v1(43.23,6.48) v1(43.36,114.3) v1(43.36,109.22) v1(43.43,70.33) v1(43.36,12.7) v1(43.36,7.62) v1(43.48,98.43) v1(43.61,19.18) v1(43.74,116.08) v1(43.74,104.14) v1(43.79,92.18) v1(43.76,89.41) v1(44.25,61.21) v1(44.25,45.34) v1(44.37,84.71) v1(44.62,76.86) v1(44.68,99.73) v1(44.78,97.03) v1(44.75,68.97) v1(44.8,20.48) v1(44.93,105.44) v1(44.91,17.78) v1(45.03,102.75) v1(45.01,90.81) v1(44.98,71.2) v1(45.26,77.51) v1(45.26,76.86) v1(45.26,76.21) v1(45.49,6.5) v1(45.64,81.28) v1(45.64,79.3) v1(45.77,83.82) v1(45.9,111.76) v1(45.91,76.86) v1(45.9,15.24) v1(46.2,92.11) v1(46.15,61.21) v1(46.3,89.41) v1(46.41,0.76) v1(46.53,6.5) v1(46.71,85.45) v1(46.66,71.32) v1(46.91,80.39) v1(47.29,78.26) v1(47.4,69.08) v1(47.47,103.23) v1(47.45,100.46) v1(47.55,116.08) v1(47.57,6.48) v1(47.8,71.25) v1(47.8,61.22) v1(48.31,79.12) v1(48.44,114.3) v1(48.44,109.22) v1(48.44,38.1) v1(48.44,33.02) v1(48.44,27.94) v1(48.44,22.86) v1(48.44,17.78) v1(48.44,5.08) v1(48.61,96.25) v1(48.59,93.48) v1(48.69,101.85) v1(48.69,52.96) v1(48.64,6.5) v1(48.75,69.22) v1(49,91.67) v1(48.97,88.9) v1(49.12,85.37) v1(49.22,82.68) v1(49.33,75.69) v1(49.58,6.5) v1(49.73,77.34) v1(49.83,94.87) v1(49.83,78.71) v1(49.88,103.15) v1(49.99,100.46) v1(49.96,68.33) v1(49.96,61.85) v1(50.09,69.47) v1(50.22,90.3) v1(50.22,0.76) v1(50.32,52.22) v1(50.32,38.89) v1(50.32,35.08) v1(50.32,25.78) v1(50.34,59.26) v1(50.37,57.58) v1(50.34,55.75) v1(50.37,53.87) v1(50.34,50.39) v1(50.34,48.44) v1(50.34,46.63) v1(50.34,44.81) v1(50.37,42.98) v1(50.37,40.74) v1(50.34,36.88) v1(50.37,33.1) v1(50.37,31.29) v1(50.34,29.41) v1(50.34,27.58) v1(50.37,23.7) v1(50.37,21.89) v1(50.39,20.09) v1(50.34,18.31) v1(50.34,16.51) v1(50.34,14.73) v1(50.34,12.93) v1(50.6,74.42) v1(50.72,66.8) v1(50.72,63.25) v1(50.98,111.76) v1(51.03,96.17) v1(50.98,86.36) v1(50.98,81.28) v1(50.98,7.62) v1(51.13,93.48) v1(51.23,68.33) v1(51.18,60.27) v1(51.36,116.08) v1(51.41,91.6) v1(51.51,88.9) v1(51.49,66.04) v1(51.49,64.01) v1(51.89,6.5) v1(52.22,57.58) v1(52.2,55.35) v1(52.22,52.65) v1(52.22,50.95) v1(52.15,48.54) v1(52.17,46.58) v1(52.22,44.65) v1(52.15,42.75) v1(52.2,34.77) v1(52.2,32.33) v1(52.22,29.34) v1(52.22,26.14) v1(52.15,23.37) v1(52.2,20.73) v1(52.15,17.83) v1(52.2,14.58) v1(52.25,39.88) v1(52.37,36.83) v1(52.5,68.07) v1(52.63,24.77) v1(52.6,21.84) v1(52.6,19.23) v1(52.68,59.18) v1(52.68,56.49) v1(52.65,54.23) v1(52.65,49.89) v1(52.68,43.71) v1(52.7,41.55) v1(52.68,38.94) v1(52.65,35.97) v1(52.7,33.35) v1(52.68,30.81) v1(52.7,27.74) v1(52.65,16.33) v1(52.81,51.79) v1(52.88,71.88) v1(52.88,47.7) v1(52.93,6.5) v1(52.96,45.8) v1(53.52,114.3) v1(53.52,79.25) v1(53.52,70.99) v1(53.52,66.04) v1(53.52,64.01) v1(53.52,52.81) v1(53.47,13.36) v1(53.52,5.08) v1(53.57,84.61) v1(53.62,83.21) v1(53.57,48.87) v1(53.54,44.93) v1(53.64,98.3) v1(53.64,96.14) v1(53.64,93.85) v1(53.64,91.69) v1(53.64,89.79) v1(53.64,77.47) v1(53.64,67.06) v1(53.77,88.52) v1(53.82,87.17) v1(53.77,86.33) v1(53.77,75.82) v1(53.9,73.66) v1(53.9,69.6) v1(53.92,6.48) v1(54.03,0.76) v1(54.33,110.34) v1(54.3,107.57) v1(54.33,72.14) v1(54.41,54.51) v1(54.43,39.28) v1(54.38,14.35) v1(54.46,59.23) v1(54.48,58.01) v1(54.46,56.31) v1(54.46,50.83) v1(54.48,42.95) v1(54.48,41.25) v1(54.48,36.91) v1(54.48,34.54) v1(54.46,32.64) v1(54.48,29.62) v1(54.48,26.34) v1(54.48,23.44) v1(54.48,20.32) v1(54.48,17.55) v1(54.64,46.3) v1(54.79,38.62) v1(54.86,42.11) v1(54.89,35.79) v1(54.84,31.04) v1(54.84,27.84) v1(54.84,24.77) v1(54.89,21.84) v1(54.91,19.08) v1(54.84,16.1) v1(54.99,55.58) v1(54.99,39.8) v1(54.99,6.5) v1(55.04,81.08) v1(55.12,51.77) v1(55.07,49.78) v1(55.07,47.75) v1(55.17,116.08) v1(55.22,57.3) v1(55.14,53.7) v1(55.19,43.94) v1(55.17,33.48) v1(55.24,59.61) v1(55.5,68.55) v1(55.47,12.93) v1(55.55,108.97) v1(55.73,45.01) v1(55.73,32.51) v1(55.75,70.26) v1(55.83,52.58) v1(55.78,48.62) v1(55.75,40.84) v1(55.75,36.88) v1(55.93,60.38) v1(55.96,6.5) v1(56.06,111.76) v1(56.11,74.7) v1(56.11,58.24) v1(56.06,7.62) v1(56.31,98.3) v1(56.31,96.14) v1(56.31,93.85) v1(56.31,91.69) v1(56.31,89.79) v1(56.26,77.47) v1(56.26,76.25) v1(56.39,86.11) v1(56.46,87.73) v1(56.62,50.8) v1(56.62,29.29) v1(56.62,25.81) v1(56.64,72.24) v1(56.64,46.84) v1(56.64,42.75) v1(56.67,38.79) v1(56.64,34.72) v1(56.67,30.99) v1(56.67,27.53) v1(56.67,24) v1(56.67,22.58) v1(56.67,21.13) v1(56.64,19.48) v1(56.67,17.81) v1(56.64,16.1) v1(56.67,14.22) v1(56.74,110.27) v1(56.77,75.08) v1(56.82,60.38) v1(56.79,56.44) v1(56.74,54.53) v1(56.84,107.57) v1(57.05,59.26) v1(57.53,52.98) v1(57.53,49.02) v1(57.53,44.98) v1(57.53,41.02) v1(57.53,36.93) v1(57.53,32.89) v1(57.58,86.18) v1(57.71,77.7) v1(57.84,0.76) v1(58.12,57.73) v1(58.19,6.48) v1(58.27,97.26) v1(58.24,94.49) v1(58.34,75.18) v1(58.52,91.67) v1(58.49,88.9) v1(58.52,72.21) v1(58.47,67.26) v1(58.52,29.67) v1(58.52,28.02) v1(58.52,23.01) v1(58.6,114.3) v1(58.62,54.61) v1(58.62,50.6) v1(58.6,38.73) v1(58.62,34.57) v1(58.55,26.37) v1(58.55,24.69) v1(58.55,21.49) v1(58.55,19.84) v1(58.55,18.21) v1(58.57,16.28) v1(58.55,14.12) v1(58.6,5.08) v1(58.65,46.56) v1(58.65,42.6) v1(58.8,86.16) v1(58.93,51.84) v1(58.88,31.7) v1(58.98,116.08) v1(58.98,84.71) v1(59.03,76) v1(59.03,47.88) v1(59,43.87) v1(58.95,39.83) v1(59.11,74.73) v1(59.05,35.86) v1(59.18,77.27) v1(59.19,6.48) v1(59.31,53.11) v1(59.33,49.07) v1(59.28,45.14) v1(59.28,41.17) v1(59.28,33.1) v1(59.36,36.96) v1(59.49,95.89) v1(59.59,72.69) v1(59.72,81.92) v1(59.69,10.77) v1(59.74,90.3) v1(59.89,12.78) v1(60.17,73.36) v1(60.15,6.5) v1(60.3,50.88) v1(60.43,54.53) v1(60.38,46.84) v1(60.4,42.77) v1(60.35,38.71) v1(60.43,34.7) v1(60.38,28.78) v1(60.43,26.82) v1(60.38,24.46) v1(60.38,22.23) v1(60.43,20.29) v1(60.43,18.36) v1(60.38,16.31) v1(60.38,14.33) v1(60.63,82.93) v1(60.63,81.03) v1(60.58,55.85) v1(60.68,97.19) v1(60.78,94.49) v1(60.93,91.6) v1(60.88,71.4) v1(61.03,88.9) v1(61.14,7.62) v1(61.14,2.54) v1(61.19,105.14) v1(61.16,102.37) v1(61.16,53.8) v1(61.19,25.55) v1(61.21,19.33) v1(61.21,17.3) v1(61.32,76) v1(61.29,52.53) v1(61.26,48.77) v1(61.32,40.74) v1(61.32,36.68) v1(61.32,32.74) v1(61.26,28.85) v1(61.26,27.76) v1(61.24,23.39) v1(61.26,21.31) v1(61.24,14.96) v1(61.32,6.48) v1(61.42,108.21) v1(61.37,44.75) v1(61.44,110.98) v1(61.52,12.85) v1(61.54,81.92) v1(61.65,0.76) v1(61.77,75.18) v1(61.82,72.34) v1(61.85,10.77) v1(62.13,50.75) v1(62.2,87.88) v1(62.2,77.19) v1(62.2,58.75) v1(62.18,56.74) v1(62.15,46.76) v1(62.15,38.68) v1(62.18,34.72) v1(62.23,30.38) v1(62.33,85.95) v1(62.28,82.04) v1(62.33,55.17) v1(62.3,6.48) v1(62.41,103.76) v1(62.66,109.6) v1(62.66,31.62) v1(62.79,116.08) v1(62.74,70.82) v1(63.12,55.32) v1(63.07,48.84) v1(63.09,44.75) v1(63.07,40.69) v1(63.07,36.6) v1(63.04,32.87) v1(63.07,27.13) v1(63.07,25.43) v1(63.07,23.47) v1(63.07,21.49) v1(63.09,19.63) v1(63.09,17.88) v1(63.07,15.98) v1(63.09,14.3) v1(63.14,54.23) v1(63.14,52.78) v1(63.25,6.5) v1(63.6,105.06) v1(63.55,88.72) v1(63.55,86.11) v1(63.6,77.67) v1(63.63,71.98) v1(63.68,114.3) v1(63.7,102.37) v1(63.68,5.08) v1(63.8,74.98) v1(63.83,57.3) v1(63.85,110.9) v1(63.93,76.71) v1(63.88,13.06) v1(63.96,108.21) v1(64.29,51.46) v1(64.29,47.4) v1(64.29,43.28) v1(64.31,39.19) v1(64.31,38.23) v1(64.29,35.08) v1(64.31,31.01) v1(64.36,72.62) v1(64.36,50.19) v1(64.49,41.96) v1(64.44,33.86) v1(64.59,45.85) v1(64.57,29.67) v1(64.69,91.82) v1(64.69,90.3) v1(64.69,88.27) v1(64.74,86.11) v1(64.8,77.47) v1(64.8,75.92) v1(64.82,59.26) v1(64.92,56.13) v1(64.87,52.5) v1(64.87,48.51) v1(64.9,44.6) v1(64.9,40.49) v1(64.92,32.46) v1(65.02,54.33) v1(64.95,36.45) v1(65,26.26) v1(65.02,24.26) v1(65.02,22.28) v1(64.97,20.5) v1(65.02,16.97) v1(65.02,15.32) v1(65.07,60.35) v1(65.07,28.17) v1(65.07,18.8) v1(65.35,13.97) v1(65.51,6.5) v1(65.46,0.76) v1(65.63,104.37) v1(65.61,101.6) v1(65.58,68.71) v1(65.61,58.14) v1(65.91,72.34) v1(65.96,82.68) v1(65.96,81.92) v1(65.96,81.03) v1(65.96,59.82) v1(66.04,51.21) v1(66.09,35.15) v1(66.07,31.14) v1(66.17,39.19) v1(66.22,7.62) v1(66.32,47.42) v1(66.32,43.51) v1(66.37,50.44) v1(66.47,42.19) v1(66.47,12.78) v1(66.52,6.5) v1(66.6,116.08) v1(66.55,46.1) v1(66.67,57) v1(66.78,38.05) v1(66.85,103) v1(66.9,49.45) v1(66.85,48.46) v1(66.9,40.77) v1(66.93,32.59) v1(66.98,54.46) v1(66.95,44.75) v1(66.95,36.22) v1(67.01,28.52) v1(67.03,23.24) v1(67.01,19.48) v1(67.11,59.33) v1(67.06,57.89) v1(67.11,55.7) v1(67.13,52.73) v1(67.11,34.34) v1(67.08,30.48) v1(67.06,26.59) v1(67.06,24.97) v1(67.06,21.31) v1(67.06,17.42) v1(67.08,15.62) v1(67.34,74.88) v1(67.36,91.82) v1(67.36,90.3) v1(67.36,88.27) v1(67.44,83.34) v1(67.39,76.86) v1(67.46,85.88) v1(67.46,84.58) v1(67.46,80.62) v1(67.46,79.35) v1(67.46,77.95) v1(67.57,6.48) v1(67.84,13.72) v1(68.05,104.3) v1(68.07,47.19) v1(68.12,43.43) v1(68.15,101.6) v1(68.15,51.13) v1(68.43,111.99) v1(68.4,109.22) v1(68.38,38.81) v1(68.63,6.48) v1(68.68,46.25) v1(68.68,42.34) v1(68.76,114.3) v1(68.76,83.82) v1(68.78,81) v1(68.76,78.74) v1(68.76,5.08) v1(68.91,85.24) v1(68.88,72.39) v1(68.86,61.98) v1(68.94,59.11) v1(68.88,57.78) v1(68.91,55.19) v1(68.88,53.44) v1(68.94,49.58) v1(68.86,48.29) v1(68.91,44.5) v1(68.94,40.67) v1(68.88,36.37) v1(68.91,33.5) v1(68.91,30.96) v1(68.88,28.17) v1(68.91,25.6) v1(68.91,22.73) v1(68.94,19.81) v1(68.94,16.69) v1(69.01,50.27) v1(69.29,47.42) v1(69.32,46.13) v1(69.29,45.21) v1(69.32,43.43) v1(69.32,39.73) v1(69.27,38.1) v1(69.29,32.39) v1(69.29,27.03) v1(69.29,24.26) v1(69.27,18.21) v1(69.29,15.42) v1(69.27,0.76) v1(69.34,56.52) v1(69.34,54.23) v1(69.37,52.5) v1(69.34,41.68) v1(69.37,34.82) v1(69.34,29.46) v1(69.34,21.21) v1(69.44,14.05) v1(69.47,12.8) v1(69.57,90.78) v1(69.54,88.02) v1(69.6,6.5) v1(69.65,110.62) v1(69.72,61.14) v1(69.9,73.28) v1(70.18,62.71) v1(70.41,116.08) v1(70.41,82.55) v1(70.79,89.41) v1(70.82,51.41) v1(70.84,111.92) v1(70.92,74.17) v1(70.94,109.22) v1(70.97,59.84) v1(71.12,57.96) v1(71.12,55.98) v1(71.12,54.18) v1(71.09,52.4) v1(71.12,50.19) v1(71.12,47.12) v1(71.12,45.82) v1(71.12,42.57) v1(71.09,41.02) v1(71.09,39.29) v1(71.12,35.84) v1(71.12,34.19) v1(71.12,32.54) v1(71.12,29.16) v1(71.12,27.13) v1(71.12,25.17) v1(71.12,21.26) v1(71.12,19.46) v1(71.12,17.55) v1(71.12,15.7) v1(71.09,14.22) v1(71.12,12.8) v1(71.17,68.71) v1(71.17,48.72) v1(71.17,44.2) v1(71.17,38.1) v1(71.15,30.94) v1(71.17,23.32) v1(71.3,86.36) v1(71.3,77.09) v1(71.3,7.62) v1(71.42,61.09) v1(71.45,62.51) v1(71.68,83.57) v1(71.88,6.5) v1(71.98,90.71) v1(72.08,88.02) v1(72.19,51.75) v1(72.31,75.82) v1(72.92,6.48) v1(72.95,70.48) v1(72.95,67.06) v1(73.05,46.02) v1(73.08,0.76) v1(73.26,43.52) v1(73.38,106.91) v1(73.35,104.14) v1(73.46,80.01) v1(73.58,81.66) v1(73.58,68.58) v1(73.84,114.3) v1(73.84,62.99) v1(73.84,38.1) v1(73.84,30.48) v1(73.84,25.4) v1(73.84,20.32) v1(73.84,15.24) v1(73.84,5.08) v1(73.92,6.48) v1(73.96,99.57) v1(73.96,94.49) v1(74.09,59.06) v1(74.22,116.08) v1(74.35,55.25) v1(74.62,109.48) v1(74.6,105.54) v1(74.65,112.25) v1(74.98,6.5) v1(75.36,72.77) v1(75.49,69.22) v1(75.52,55.94) v1(75.79,106.84) v1(75.79,48.16) v1(75.87,110.87) v1(75.89,104.14) v1(76,66.93) v1(75.95,6.5) v1(76.12,68.07) v1(76.38,43.18) v1(76.38,35.56) v1(76.38,33.02) v1(76.38,27.94) v1(76.38,22.86) v1(76.38,17.78) v1(76.38,7.62) v1(76.5,97.03) v1(76.5,82.8) v1(76.61,62.05) v1(76.63,53.59) v1(76.89,59.56) v1(76.85,39.93) v1(76.89,0.76) v1(77.01,62.86) v1(77.06,112.17) v1(77.16,109.48) v1(77.14,67.18) v1(77.14,31.88) v1(77.27,80.9) v1(77.27,68.58) v1(77.65,61.21) v1(78.03,116.08) v1(78.13,46.02) v1(78.21,6.5) v1(78.33,104.12) v1(78.28,71.75) v1(78.92,114.3) v1(78.92,55.88) v1(78.92,50.8) v1(78.92,40.64) v1(78.92,33.02) v1(78.92,30.48) v1(78.92,25.4) v1(78.92,20.32) v1(78.92,15.24) v1(78.92,8.51) v1(79.04,99.57) v1(79.04,94.49) v1(79.11,52.35) v1(79.17,72.64) v1(79.19,6.48) v1(79.55,102.74) v1(79.68,69.98) v1(79.68,60.07) v1(79.68,13.08) v1(79.93,83.95) v1(80.06,77.34) v1(80.16,6.48) v1(80.7,0.76) v1(80.75,104.04) v1(81.33,56.26) v1(81.38,112.63) v1(81.35,109.86) v1(81.42,90.06) v1(81.42,87.52) v1(81.46,85.6) v1(81.46,71.75) v1(81.46,53.34) v1(81.46,48.26) v1(81.46,43.18) v1(81.46,38.1) v1(81.46,22.86) v1(81.46,17.78) v1(81.46,7.62) v1(81.46,2.54) v1(81.84,116.08) v1(82.02,93.2) v1(81.97,59.06) v1(81.97,10.8) v1(82.22,75.06) v1(82.6,111.25) v1(82.73,79.63) v1(82.85,25.02) v1(82.98,30.23) v1(83.11,8.51) v1(83.24,13.08) v1(83.79,112.55) v1(83.82,95) v1(83.8,45.86) v1(83.89,109.86) v1(83.87,78.11) v1(84,114.3) v1(84,84.58) v1(84,55.88) v1(84,53.47) v1(84,50.8) v1(84,40.64) v1(84,33.02) v1(84,20.32) v1(84,15.24) v1(84.12,91.44) v1(84.09,90.06) v1(84.09,87.52) v1(84.12,85.6) v1(84.12,80.9) v1(84.12,67.31) v1(84.12,62.86) v1(84.3,106.15) v1(84.28,103.38) v1(84.51,0.76) v1(85.14,69.22) v1(85.39,60.83) v1(85.52,104.78) v1(85.61,96.79) v1(85.65,116.08) v1(85.72,93.22) v1(85.9,79.88) v1(85.9,74.8) v1(86.03,84.71) v1(86.03,82.04) v1(86.54,58.42) v1(86.54,53.34) v1(86.54,48.26) v1(86.54,43.18) v1(86.54,38.1) v1(86.54,17.78) v1(86.54,2.54) v1(86.59,111.99) v1(86.56,109.22) v1(86.71,106.08) v1(86.82,103.38) v1(86.79,30.23) v1(86.92,25.15) v1(86.92,8.38) v1(87.03,91.21) v1(87.1,22.99) v1(87.17,87.63) v1(87.41,98.59) v1(87.39,42.27) v1(87.52,95.01) v1(87.68,46.74) v1(87.68,32.99) v1(87.81,110.62) v1(88.19,67.69) v1(88.19,62.48) v1(88.32,12.32) v1(88.32,0.76) v1(88.44,77.34) v1(88.44,65.02) v1(88.57,84.71) v1(88.57,82.04) v1(88.7,80.14) v1(89,111.92) v1(89.08,114.3) v1(89.1,109.22) v1(89.08,55.88) v1(89.08,50.8) v1(89.08,40.64) v1(89.08,20.32) v1(89.08,15.24) v1(89.08,10.8) v1(89.08,5.08) v1(89.21,100.38) v1(89.2,60.33) v1(89.32,96.81) v1(89.38,103.99) v1(89.46,116.08) v1(89.59,35.56) v1(89.59,8.38) v1(90.47,67.69) v1(90.47,14.48) v1(90.62,94.8) v1(90.62,91.21) v1(90.62,87.62) v1(90.6,62.48) v1(90.6,30.1) v1(90.86,45.09) v1(90.86,10.29) v1(91,102.18) v1(90.98,82.04) v1(90.98,79.88) v1(90.98,74.8) v1(91.11,98.61) v1(91.11,84.71) v1(91.11,25.02) v1(91.62,111.76) v1(91.62,58.42) v1(91.62,53.34) v1(91.62,48.26) v1(91.62,43.18) v1(91.62,38.1) v1(91.62,33.02) v1(91.62,17.78) v1(91.62,7.62) v1(91.62,2.54) v1(92.13,0.76) v1(92.27,69.36) v1(92.34,60.74) v1(92.67,86.14) v1(92.8,103.98) v1(92.76,82.42) v1(92.94,112.5) v1(92.91,100.4) v1(92.89,14.61) v1(93.14,17.15) v1(93.27,116.08) v1(93.27,97.41) v1(93.4,77.22) v1(93.67,67.08) v1(93.74,63.03) v1(94.07,71.16) v1(94.16,114.3) v1(94.16,111.12) v1(94.22,91.21) v1(94.14,58.95) v1(94.16,55.88) v1(94.16,50.8) v1(94.16,20.32) v1(94.16,10.16) v1(94.16,5.08) v1(94.28,94.62) v1(94.41,29.97) v1(94.47,87.94) v1(94.6,105.77) v1(94.58,84.24) v1(94.54,46.48) v1(94.7,102.2) v1(94.79,65.02) v1(94.79,44.45) v1(95.17,115.19) v1(95.35,112.43) v1(95.46,68.87) v1(95.54,61.23) v1(95.45,33.07) v1(95.54,99.46) v1(95.55,79.88) v1(95.55,74.8) v1(95.81,72.64) v1(95.94,0.76) v1(96.06,57.4) v1(96.26,89.74) v1(96.39,107.57) v1(96.37,86.03) v1(96.5,103.99) v1(96.44,18.16) v1(96.7,53.34) v1(96.7,48.26) v1(96.7,43.18) v1(96.7,12.7) v1(96.7,7.62) v1(96.7,2.54) v1(96.82,96.77) v1(96.82,26.04) v1(96.95,93.34) v1(97.21,67.44) v1(97.21,62.36) v1(98.06,91.53) v1(98.09,77.34) v1(98.17,87.83) v1(98.3,105.79) v1(98.35,83.06) v1(98.35,72.64) v1(98.35,69.98) v1(98.35,11.68) v1(98.35,8.26) v1(98.35,4.45) v1(98.35,0.76) v1(98.6,60.07) v1(98.6,57.4) v1(98.73,13.46) v1(99.13,103.05) v1(99.13,99.46) v1(99.13,95.87) v1(99.24,55.88) v1(99.24,50.8) v1(99.24,40.64) v1(99.24,35.56) v1(99.24,30.48) v1(99.24,27.56) v1(99.24,18.54) v1(99.24,15.24) v1(99.75,68.2) v1(99.75,64.9) v1(99.75,61.59) v1(99.86,93.33) v1(99.96,89.63) v1(100.63,79.88) v1(100.63,74.8) v1(100.89,72.64) v1(100.89,69.98) v1(100.89,44.96) v1(101.14,60.07) v1(101.14,57.4) v1(101.27,86.49) v1(101.65,101.98) v1(101.65,95.12) v1(101.76,91.42) v1(101.78,53.34) v1(101.78,48.26) v1(101.78,43.18) v1(101.78,17.78) v1(102.29,67.44) v1(102.29,62.36) v1(102.72,99.46) v1(102.67,13.46) v1(102.92,77.22) v1(103.43,72.64) v1(103.43,69.98) v1(103.43,42.42) v1(103.45,96.92) v1(103.56,93.22) v1(103.68,60.07) v1(103.68,57.4) v1(103.94,89.66) v1(103.94,84.58) v1(104.19,64.77) v1(104.32,55.88) v1(104.32,50.8) v1(104.32,40.64) v1(104.32,27.94) v1(104.32,20.32) v1(104.32,15.24) v1(104.57,104.78) v1(105.24,98.72) v1(105.33,79.63) v1(105.33,74.55) v1(105.35,95.02) v1(105.97,72.64) v1(105.97,69.98) v1(106.22,60.07) v1(106.22,57.4) v1(106.48,92.46) v1(106.48,87.12) v1(106.48,68.2) v1(106.48,13.46) v1(106.6,82.3) v1(106.6,61.59) v1(106.71,36.45) v1(106.65,34.19) v1(106.86,53.34) v1(106.86,48.26) v1(106.86,43.18) v1(106.86,38.1) v1(106.91,29.36) v1(106.86,22.86) v1(106.86,17.78) v1(107.15,96.81) v1(107.52,40.51) v1(107.75,32) v1(107.87,77.09) v1(108,42.16) v1(108.38,64.9) v1(108.51,72.64) v1(108.51,69.98) v1(108.76,60.07) v1(108.76,57.4) v1(109.02,89.66) v1(109.02,84.58) v1(109.4,55.88) v1(109.4,50.8) v1(109.4,30.78) v1(109.4,20.32) v1(109.4,15.24) v1(109.63,35.86) v1(109.63,33.53) v1(109.78,67.56) v1(109.78,62.48) v1(110.16,27.69) v1(110.29,13.46) v1(110.41,79.63) v1(110.41,74.55) v1(110.67,35.18) v1(111.05,72.64) v1(111.05,69.98) v1(111.33,90.3) v1(111.3,60.07) v1(111.3,57.4) v1(111.35,93.07) v1(111.51,38.68) v1(111.56,87.12) v1(111.94,53.34) v1(111.94,48.26) v1(111.94,22.86) v1(111.94,17.78) v1(112.32,65.02) v1(112.57,91.69) v1(112.57,68.2) v1(112.57,61.47) v1(112.57,32.64) v1(113.59,72.64) v1(113.59,69.98) v1(113.77,92.99) v1(113.87,90.3) v1(113.84,60.07) v1(113.84,57.4) v1(113.97,13.46) v1(114.1,96.39) v1(114.48,81.28) v1(114.48,76.2) v1(114.48,55.88) v1(114.48,50.8) v1(114.48,20.32) v1(114.73,65.02) v1(114.86,67.56) v1(114.86,62.48) v1(115.24,95.25) v1(115.24,27.69) v1(116.13,72.64) v1(116.13,69.98) v1(116.38,94.11) v1(116.38,60.07) v1(116.38,57.4) v1(117.02,78.74) v1(116.94,65.05) v1(117.02,48.26) v1(117.02,22.86) v1(117.04,62.36) v1(117.65,92.84) v1(117.65,32.64) v1(118.46,66.4) v1(118.44,63.63) v1(119.3,91.19) v1(119.56,50.8) v1(119.56,30.48) v1(119.56,27.94) v1(119.56,22.86) v1(119.68,65.02) v1(120.88,66.32) v1(120.98,63.63) v1(121.08,83.95) v1(121.08,81.03) v1(121.11,78.49) v1(121.11,51.69) v1(121.11,49.15) v1(121.11,46.61) v1(121.11,42.93) v1(121.11,40.39) v1(121.11,37.85) v1(121.11,34.42) v1(121.11,31.88) v1(121.11,29.34) v1(121.11,26.8) v1(121.11,24.26) v1(121.11,22.23) v1(121.11,19.69) v1(121.21,89.28) v2(32.94,49.66) v2(32.94,48.64) v2(58.01,66.29) v2(58.01,65.13) v2(58.01,63.96) v2(58.01,62.79) v2(59.18,67.46) v2(59.18,66.29) v2(59.18,65.13) v2(59.18,63.96) v2(59.18,62.79) v2(59.18,61.62) v2(60.35,67.46) v2(60.35,66.29) v2(60.35,65.13) v2(60.35,63.96) v2(60.35,62.79) v2(60.35,61.62) v2(61.52,67.46) v2(61.52,66.29) v2(61.52,65.13) v2(61.52,63.96) v2(61.52,62.79) v2(61.52,61.62) v2(62.69,67.46) v2(62.69,66.29) v2(62.69,65.13) v2(62.69,63.96) v2(62.69,62.79) v2(62.69,61.62) v2(63.86,66.29) v2(63.86,65.13) v2(63.86,63.96) v2(63.86,62.79) v3(0.6,76.64) v3(0.6,75.75) v3(0.6,74.86) v3(0.6,71.07) v3(0.6,70.19) v3(0.6,69.3) v3(0.6,60.76) v3(0.6,59.87) v3(0.6,58.98) v3(0.6,55.2) v3(0.6,54.31) v3(0.6,53.42) v3(1.36,76.64) v3(1.36,75.75) v3(1.36,74.86) v3(1.36,71.07) v3(1.36,70.19) v3(1.36,69.3) v3(1.36,60.76) v3(1.36,59.87) v3(1.36,58.98) v3(1.36,55.2) v3(1.36,54.31) v3(1.36,53.42) v3(2.25,76.66) v3(2.25,75.75) v3(2.25,74.88) v3(2.25,71.1) v3(2.25,60.79) v3(2.25,59.87) v3(2.25,59.01) v3(2.25,55.22) v3(2.25,54.31) v3(2.25,53.45) v3(3.14,76.66) v3(3.14,75.77) v3(3.14,74.88) v3(3.14,71.1) v3(3.14,70.21) v3(3.14,69.32) v3(3.14,60.79) v3(3.14,59.9) v3(3.14,59.01) v3(3.14,55.22) v3(3.14,54.34) v3(3.14,53.45) v3(3.9,76.66) v3(3.9,75.77) v3(3.9,74.88) v3(3.9,71.1) v3(3.9,70.21) v3(3.9,69.32) v3(3.9,60.79) v3(3.9,59.9) v3(3.9,59.01) v3(3.9,55.22) v3(3.9,54.34) v3(3.9,53.45) v3(10.76,105.96) v3(11.3,105.42) v3(11.39,106.59) v3(11.92,106.05) v3(12.01,107.21) v3(11.94,104.81) v3(12.55,106.67) v3(12.55,105.42) v3(12.57,104.18) v3(13.2,106.06) v3(13.2,104.81) v3(13.83,105.44) v3(13.74,104.27) v3(14.37,104.9) v3(14.69,109.89) v3(15.23,109.35) v3(15.32,110.52) v3(15.86,109.98) v3(15.88,108.74) v3(15.95,111.15) v3(16.49,110.61) v3(16.49,109.35) v3(16.5,108.11) v3(17.13,110) v3(17.13,108.74) v3(17.04,107.57) v3(17.67,108.2) v3(17.76,109.37) v3(18.3,108.83) v3(20.88,15.11) v3(21.77,14.22) v3(22.66,27.43) v3(23.04,14.22) v3(24.94,14.22) v3(26.09,14.22) v3(27.1,15.11) v3(28.63,30.23) v3(30.4,17.15) v3(31.93,17.65) v3(33.32,34.42) v3(34.34,35.31) v3(34.47,27.56) v3(35.48,37.21) v3(35.86,27.56) v3(36.12,35.31) v3(36.63,36.58) v3(37.13,34.54) v3(37.65,38.7) v3(37.65,37.5) v3(37.77,34.29) v3(38.15,38.1) v3(38.28,28.45) v3(38.65,38.7) v3(38.65,37.5) v3(39.17,27.56) v3(39.8,42.67) v3(39.8,26.42) v3(40.18,27.43) v3(40.82,41.53) v3(42.21,26.42) v3(42.6,27.43) v3(42.72,33.78) v3(43.48,40.39) v3(43.48,37.85) v3(43.48,36.7) v3(43.87,33.78) v3(44.37,39.5) v3(44.37,35.56) v3(44.37,34.54) v3(45.52,23.24) v3(46.06,29.58) v3(46.06,28.58) v3(46.66,29.08) v3(47.26,29.58) v3(47.26,28.58) v3(47.68,26.8) v3(48.69,31.88) v3(95.69,110.2) v3(96.23,110.74) v3(96.32,109.57) v3(96.86,111.37) v3(96.86,110.11) v3(96.95,108.94) v3(97.47,112.01) v3(97.47,110.76) v3(97.49,109.48) v3(98.01,112.55) v3(98.1,111.38) v3(98.12,110.11) v3(98.64,111.92) v3(98.73,110.76) v3(99.27,111.29) v3(99.63,106.27) v3(100.17,106.8) v3(100.26,105.64) v3(100.8,107.43) v3(100.8,106.18) v3(100.88,105.01) v3(101.41,108.08) v3(101.41,106.82) v3(101.42,105.55) v3(101.94,108.62) v3(102.03,107.45) v3(102.05,106.18) v3(102.57,107.99) v3(102.66,106.82) v3(103.2,107.36) v3(104.58,101.31) v3(105.12,101.85) v3(105.21,100.68) v3(105.75,102.48) v3(105.75,101.22) v3(105.84,100.05) v3(106.36,103.12) v3(106.36,101.87) v3(106.38,100.59) v3(106.9,103.66) v3(106.99,102.49) v3(107.01,101.22) v3(107.53,103.03) v3(107.62,101.87) v3(108.16,102.4) v3(108.52,97.38) v3(109.06,97.91) v3(109.15,96.75) v3(109.69,98.54) v3(109.69,97.29) v3(109.78,96.12) v3(110.3,99.19) v3(110.3,97.93) v3(110.31,96.66) v3(110.83,99.73) v3(110.92,98.56) v3(110.94,97.29) v3(111.46,99.1) v3(111.55,97.93) v3(112.09,98.47) v3(118.02,74.95) v3(118.02,74.06) v3(118.02,73.17) v3(118.02,69.39) v3(118.02,68.5) v3(118.02,67.61) v3(118.02,62.38) v3(118.02,61.49) v3(118.02,60.6) v3(118.02,56.82) v3(118.02,55.93) v3(118.02,55.04) v3(118.78,74.95) v3(118.78,74.06) v3(118.78,73.17) v3(118.78,69.39) v3(118.78,68.5) v3(118.78,67.61) v3(118.78,62.38) v3(118.78,61.49) v3(118.78,60.6) v3(118.78,56.82) v3(118.78,55.93) v3(118.78,55.04) v3(119.67,74.95) v3(119.67,74.09) v3(119.67,73.17) v3(119.67,69.39) v3(119.67,68.53) v3(119.67,67.61) v3(119.67,62.38) v3(119.67,61.52) v3(119.67,60.6) v3(119.67,56.82) v3(119.67,55.95) v3(119.67,55.04) v3(120.56,74.98) v3(120.56,74.09) v3(120.56,73.2) v3(120.56,69.41) v3(120.56,68.53) v3(120.56,67.64) v3(120.56,62.4) v3(120.56,61.52) v3(120.56,60.63) v3(120.56,56.84) v3(120.56,55.95) v3(120.56,55.06) v3(121.32,74.98) v3(121.32,74.09) v3(121.32,73.2) v3(121.32,69.41) v3(121.32,68.53) v3(121.32,67.64) v3(121.32,62.4) v3(121.32,61.52) v3(121.32,60.63) v3(121.32,56.84) v3(121.32,55.95) v3(121.32,55.06)
